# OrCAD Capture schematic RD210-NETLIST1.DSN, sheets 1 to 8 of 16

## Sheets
1 16: size Custom
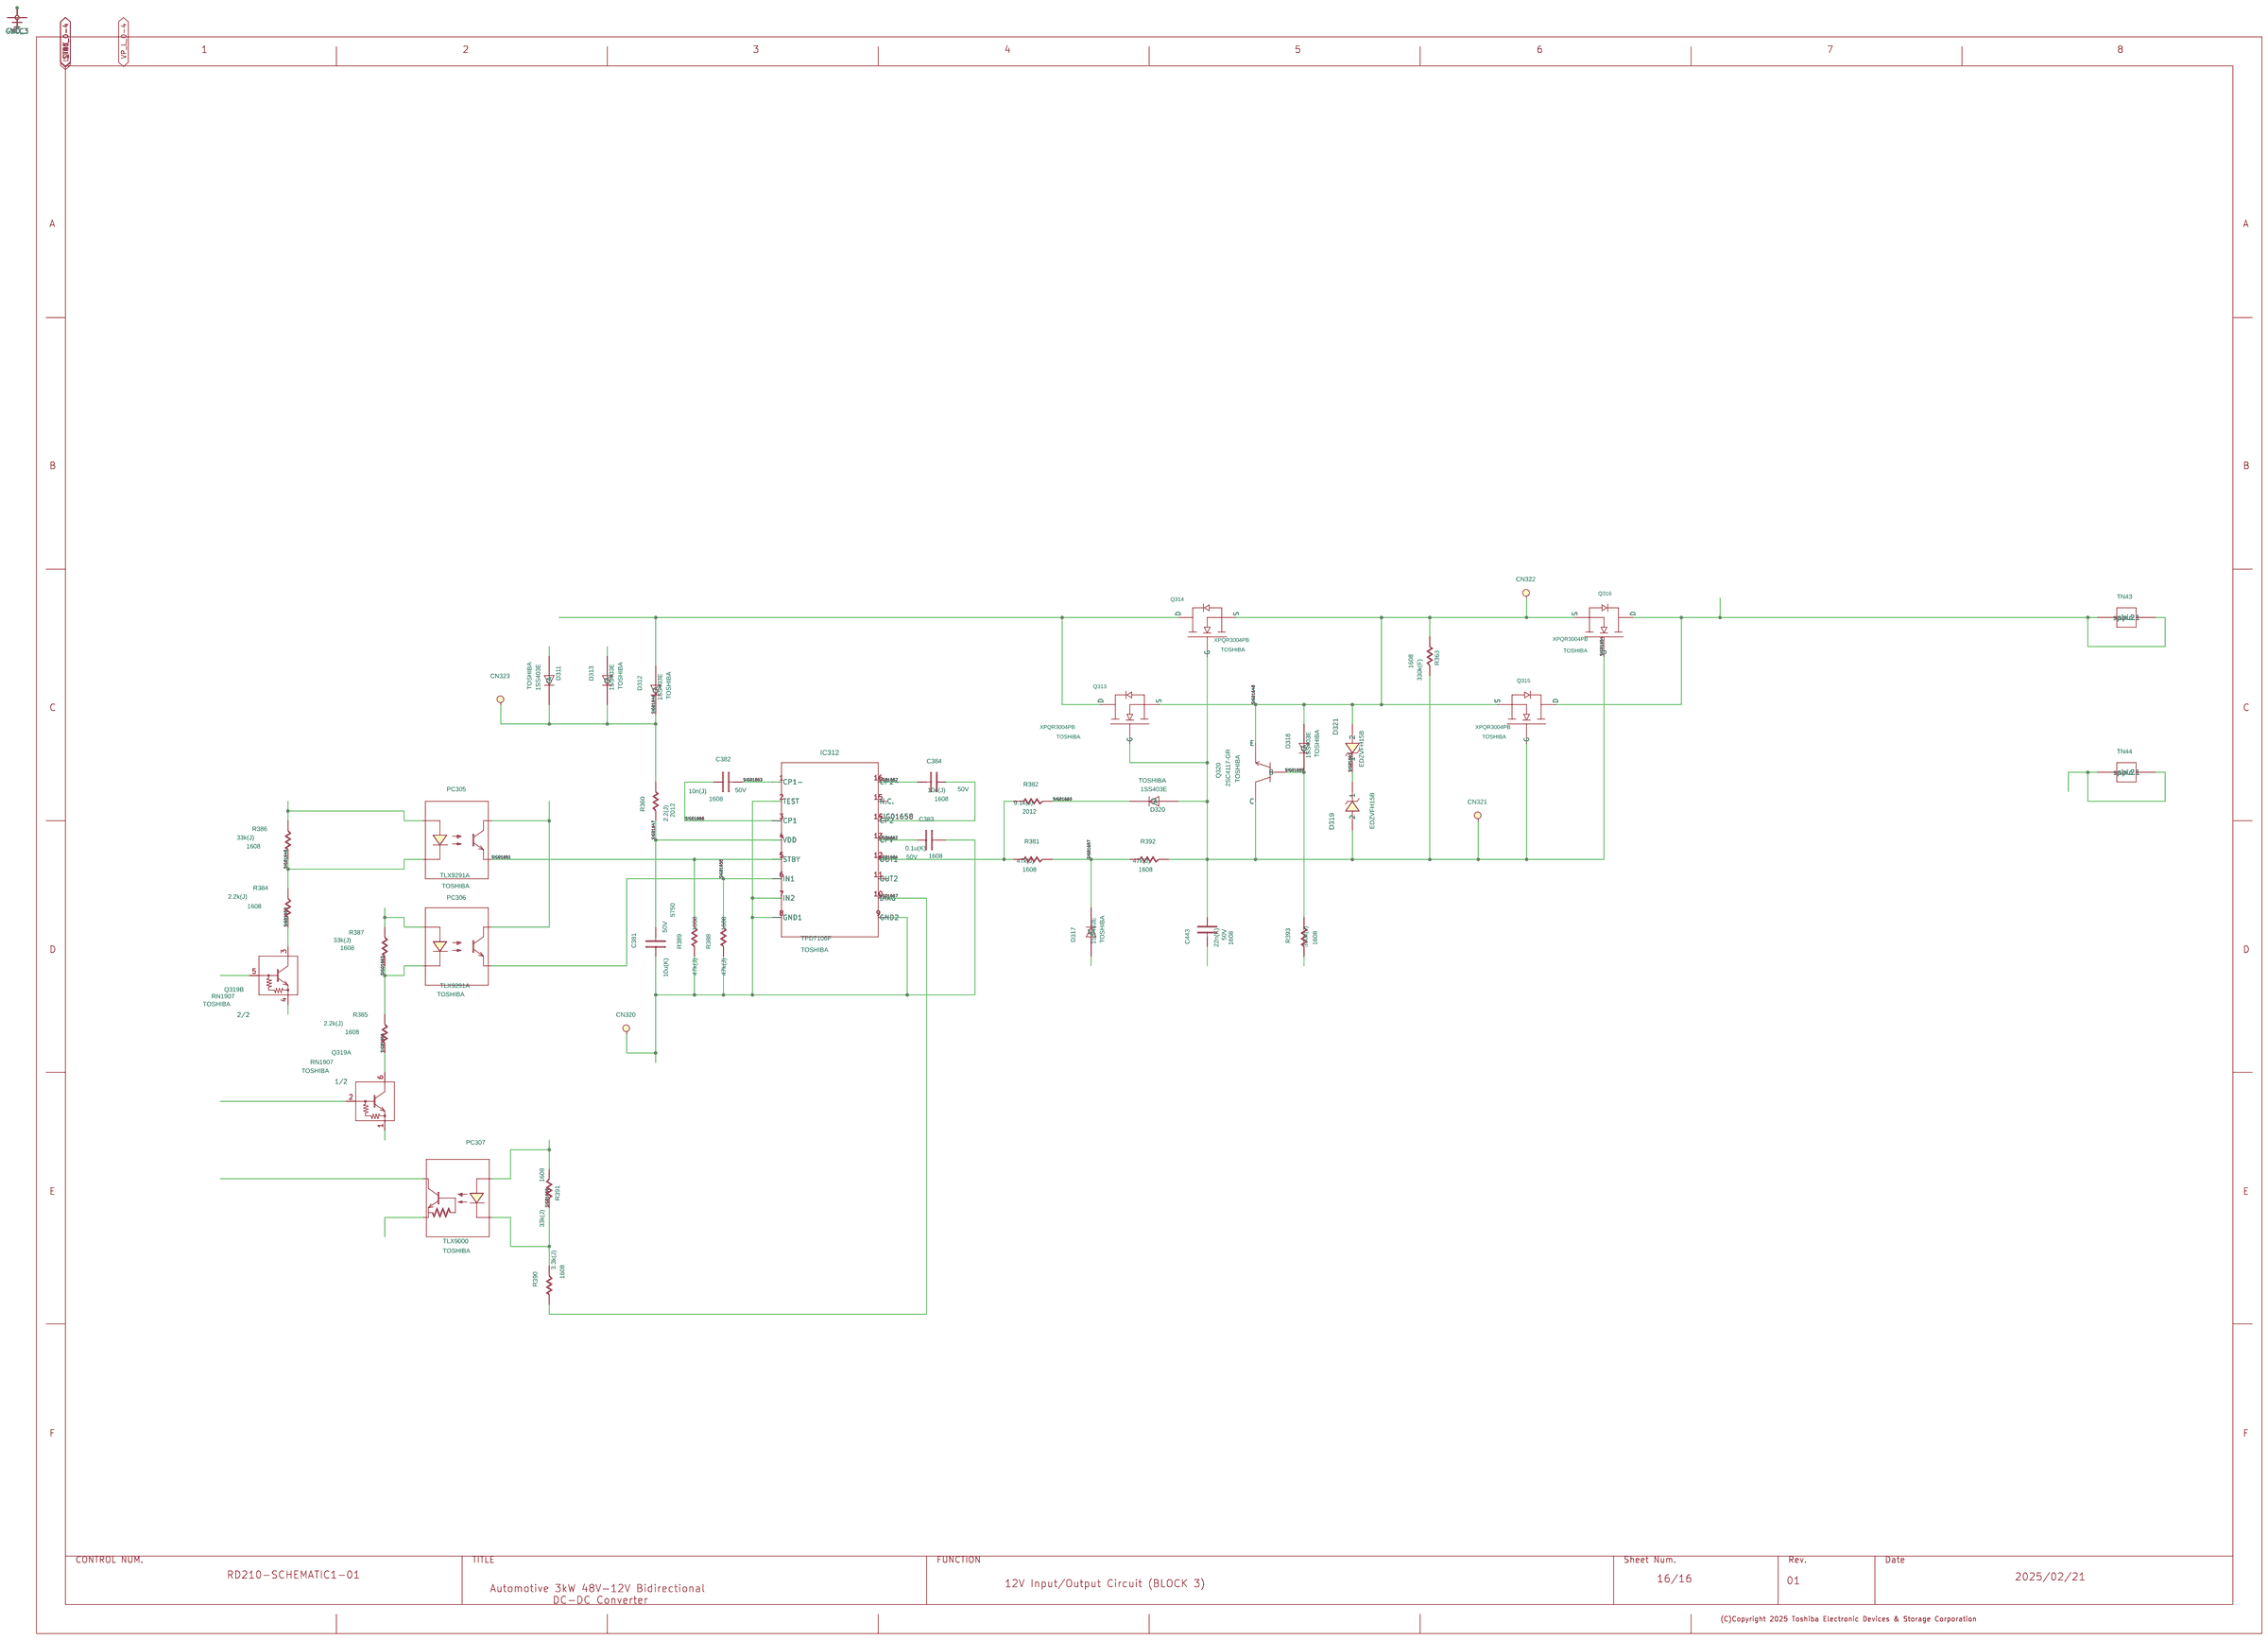
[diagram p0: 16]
2 15: size Custom
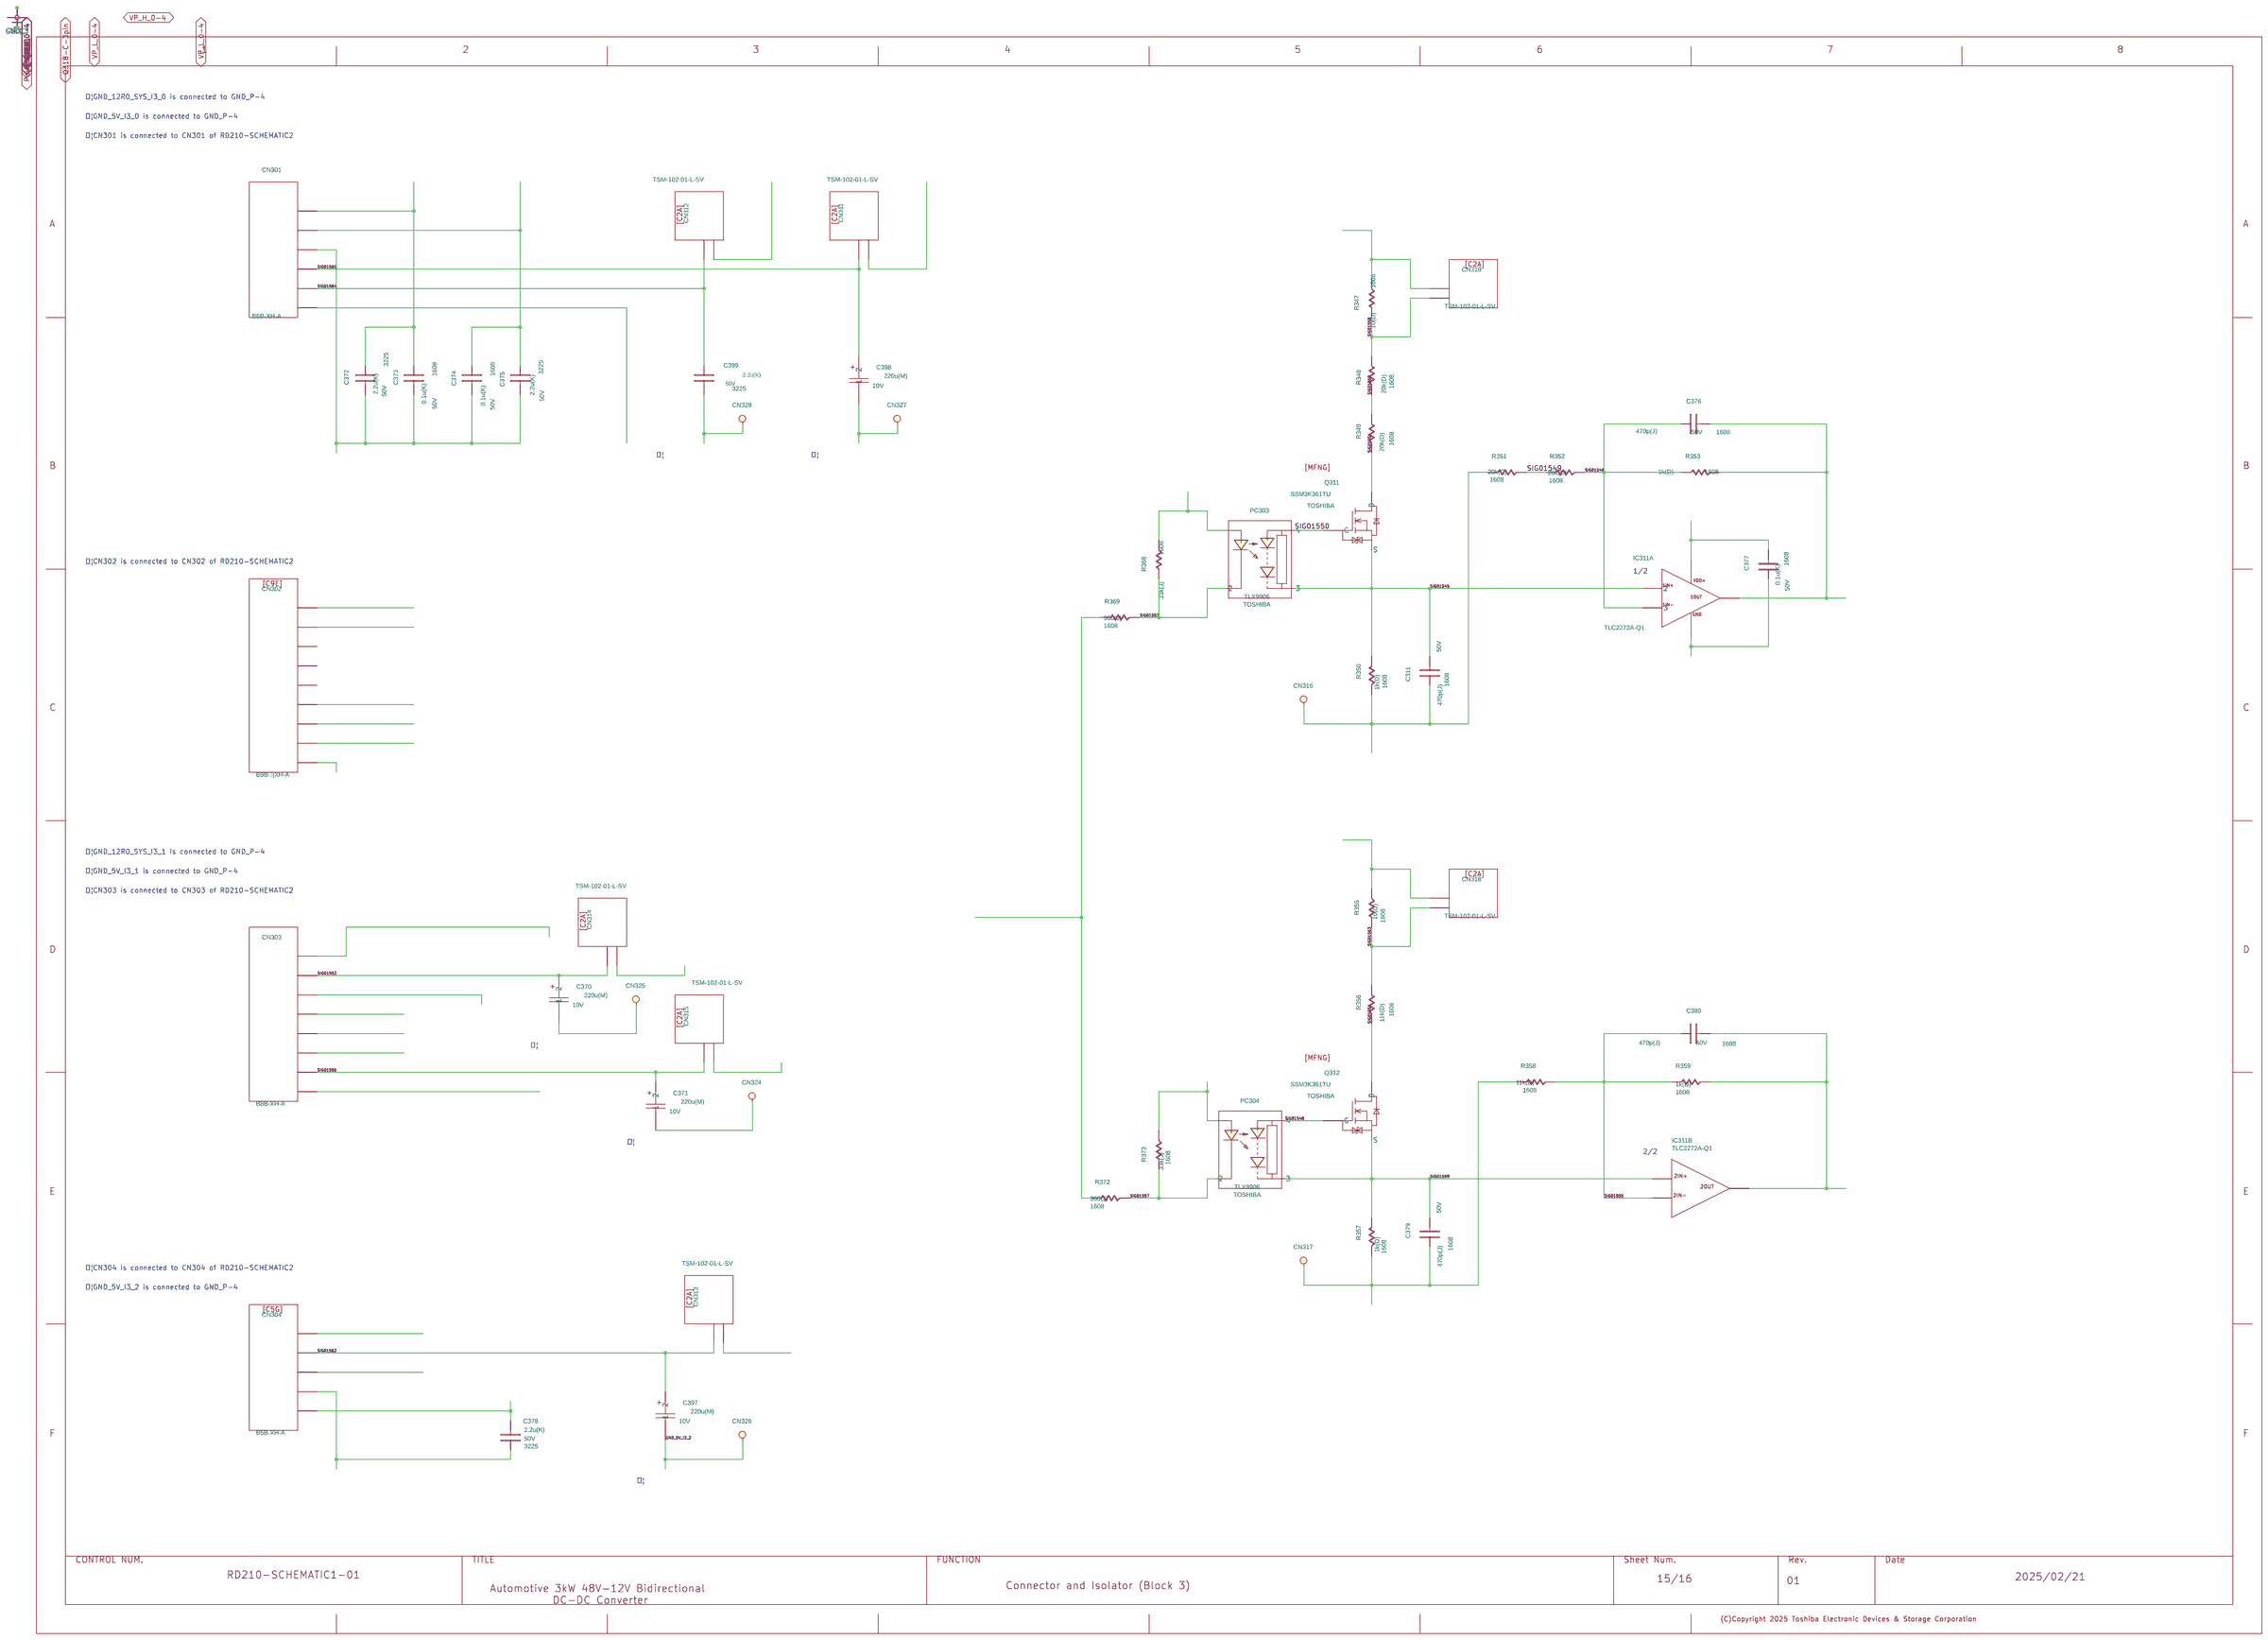
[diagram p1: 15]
3 14: size Custom
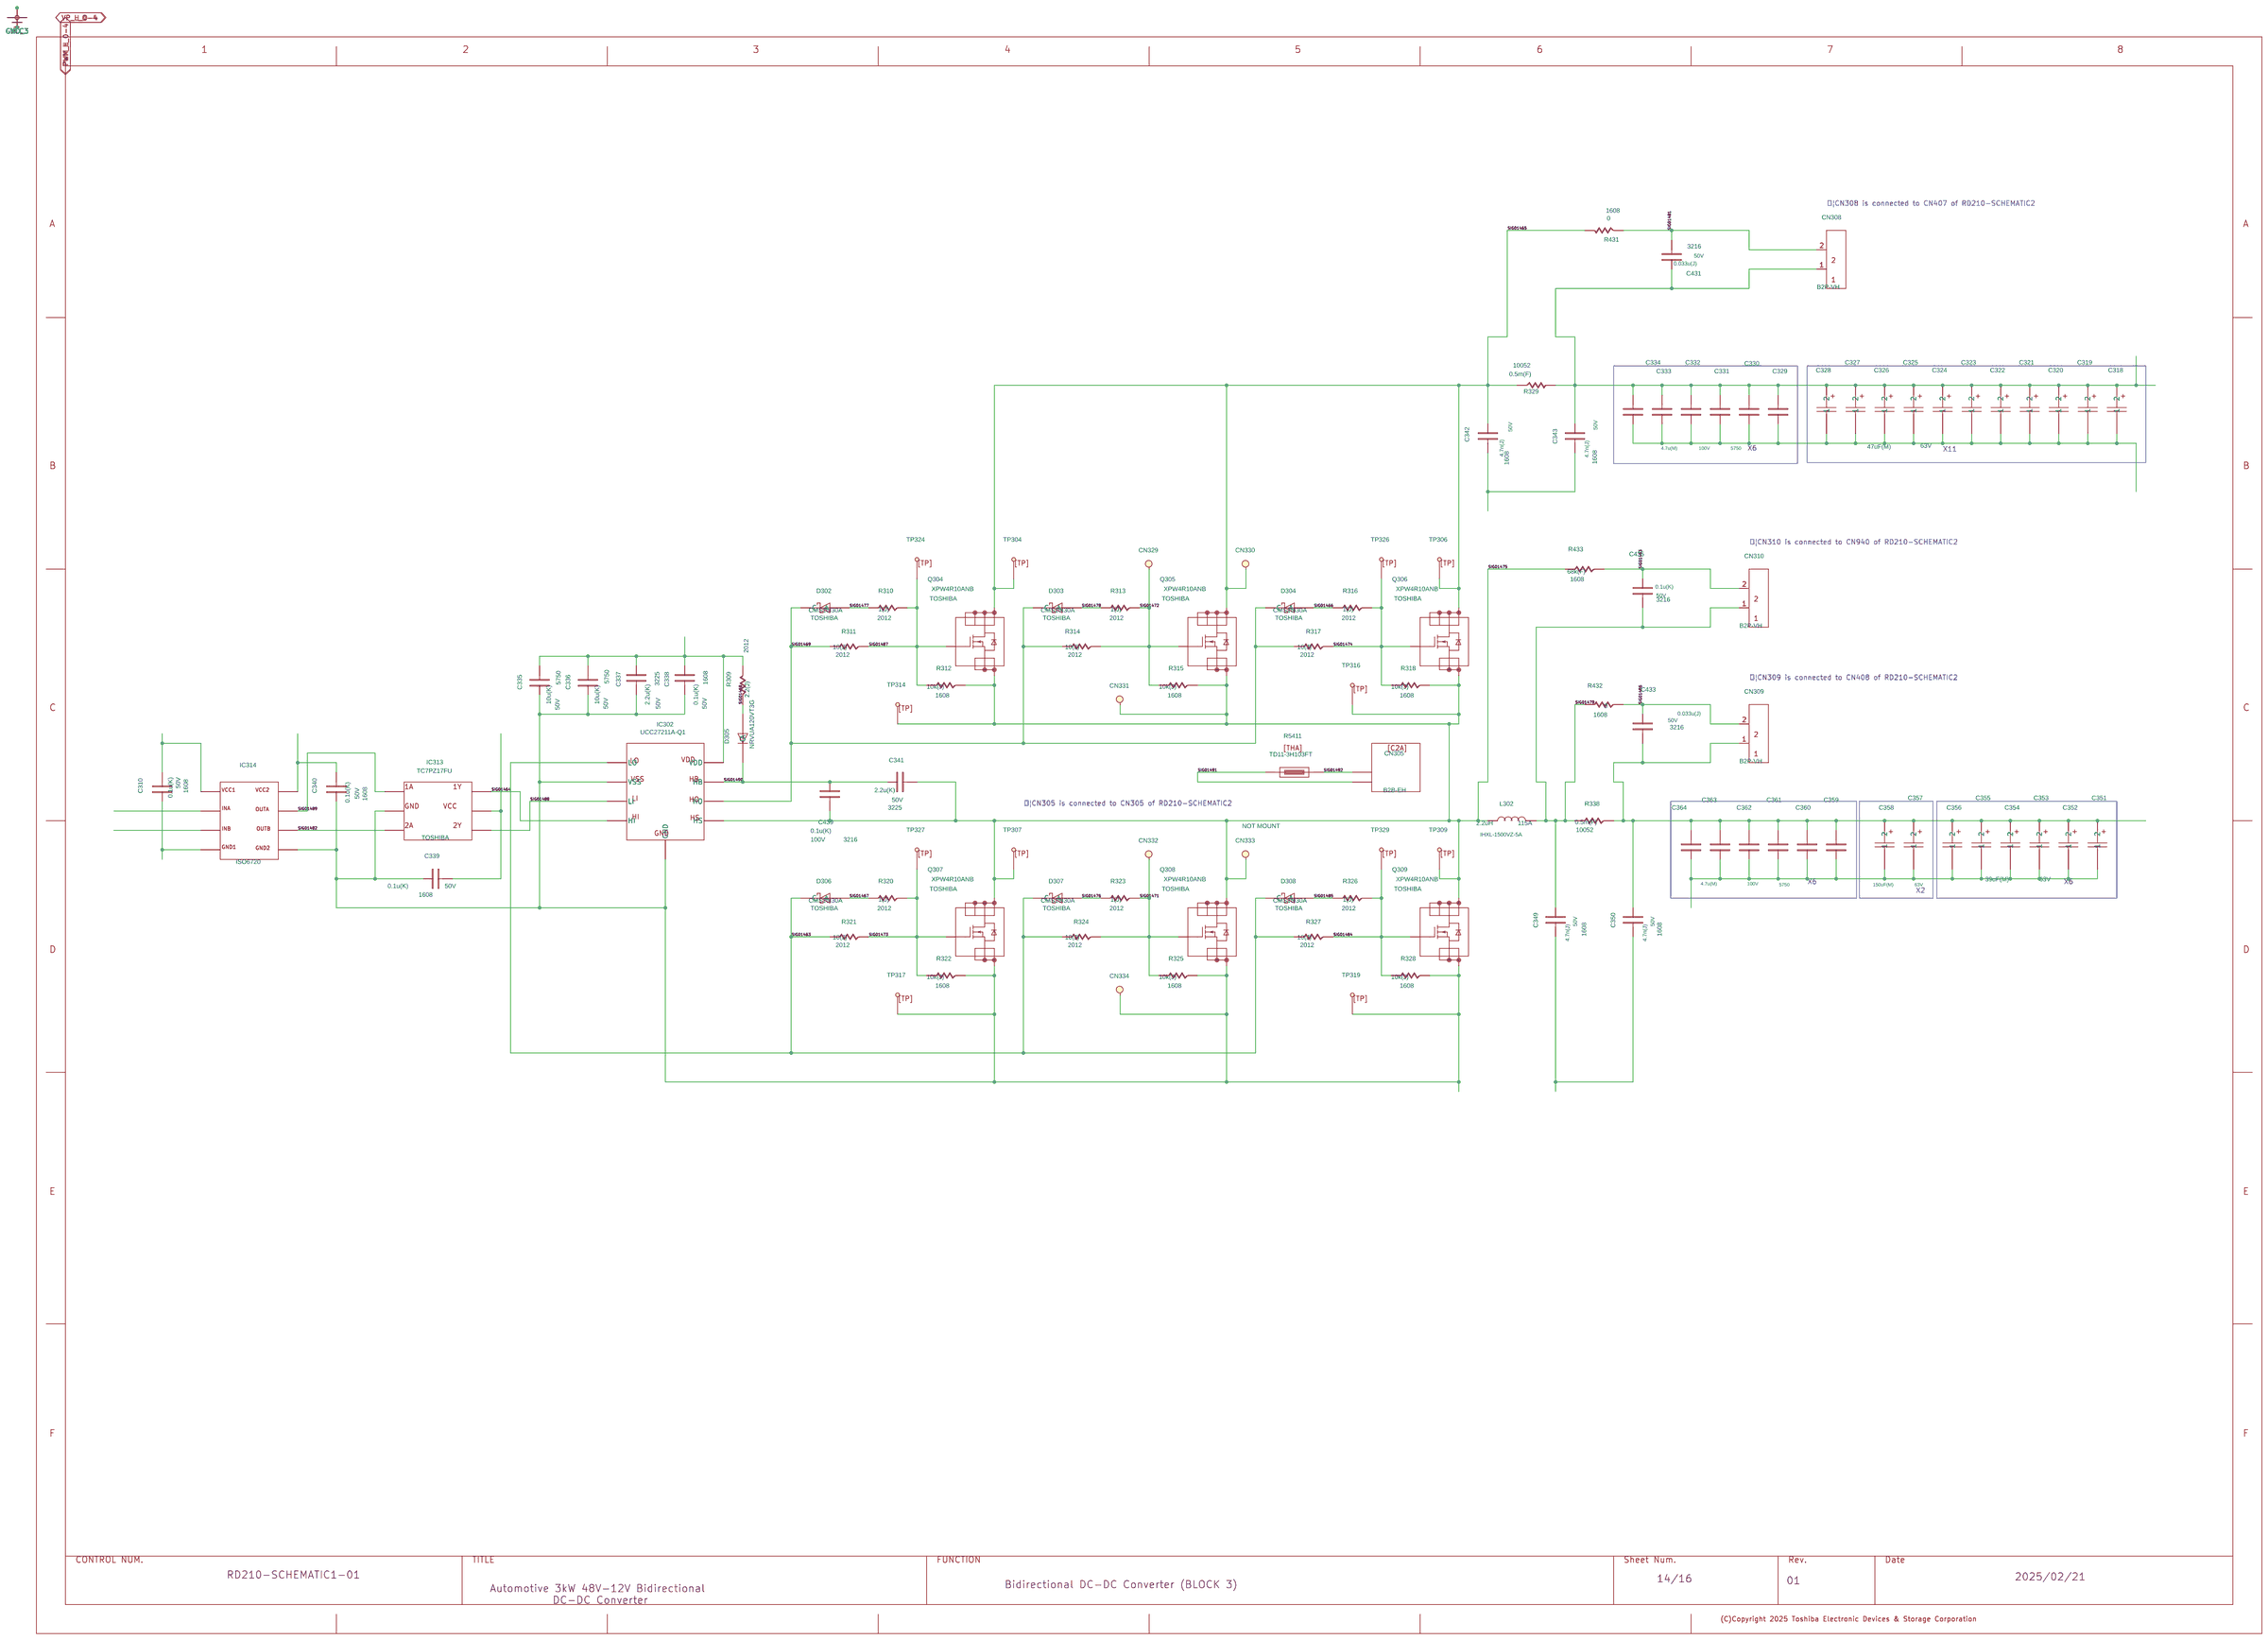
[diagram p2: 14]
4 13: size Custom
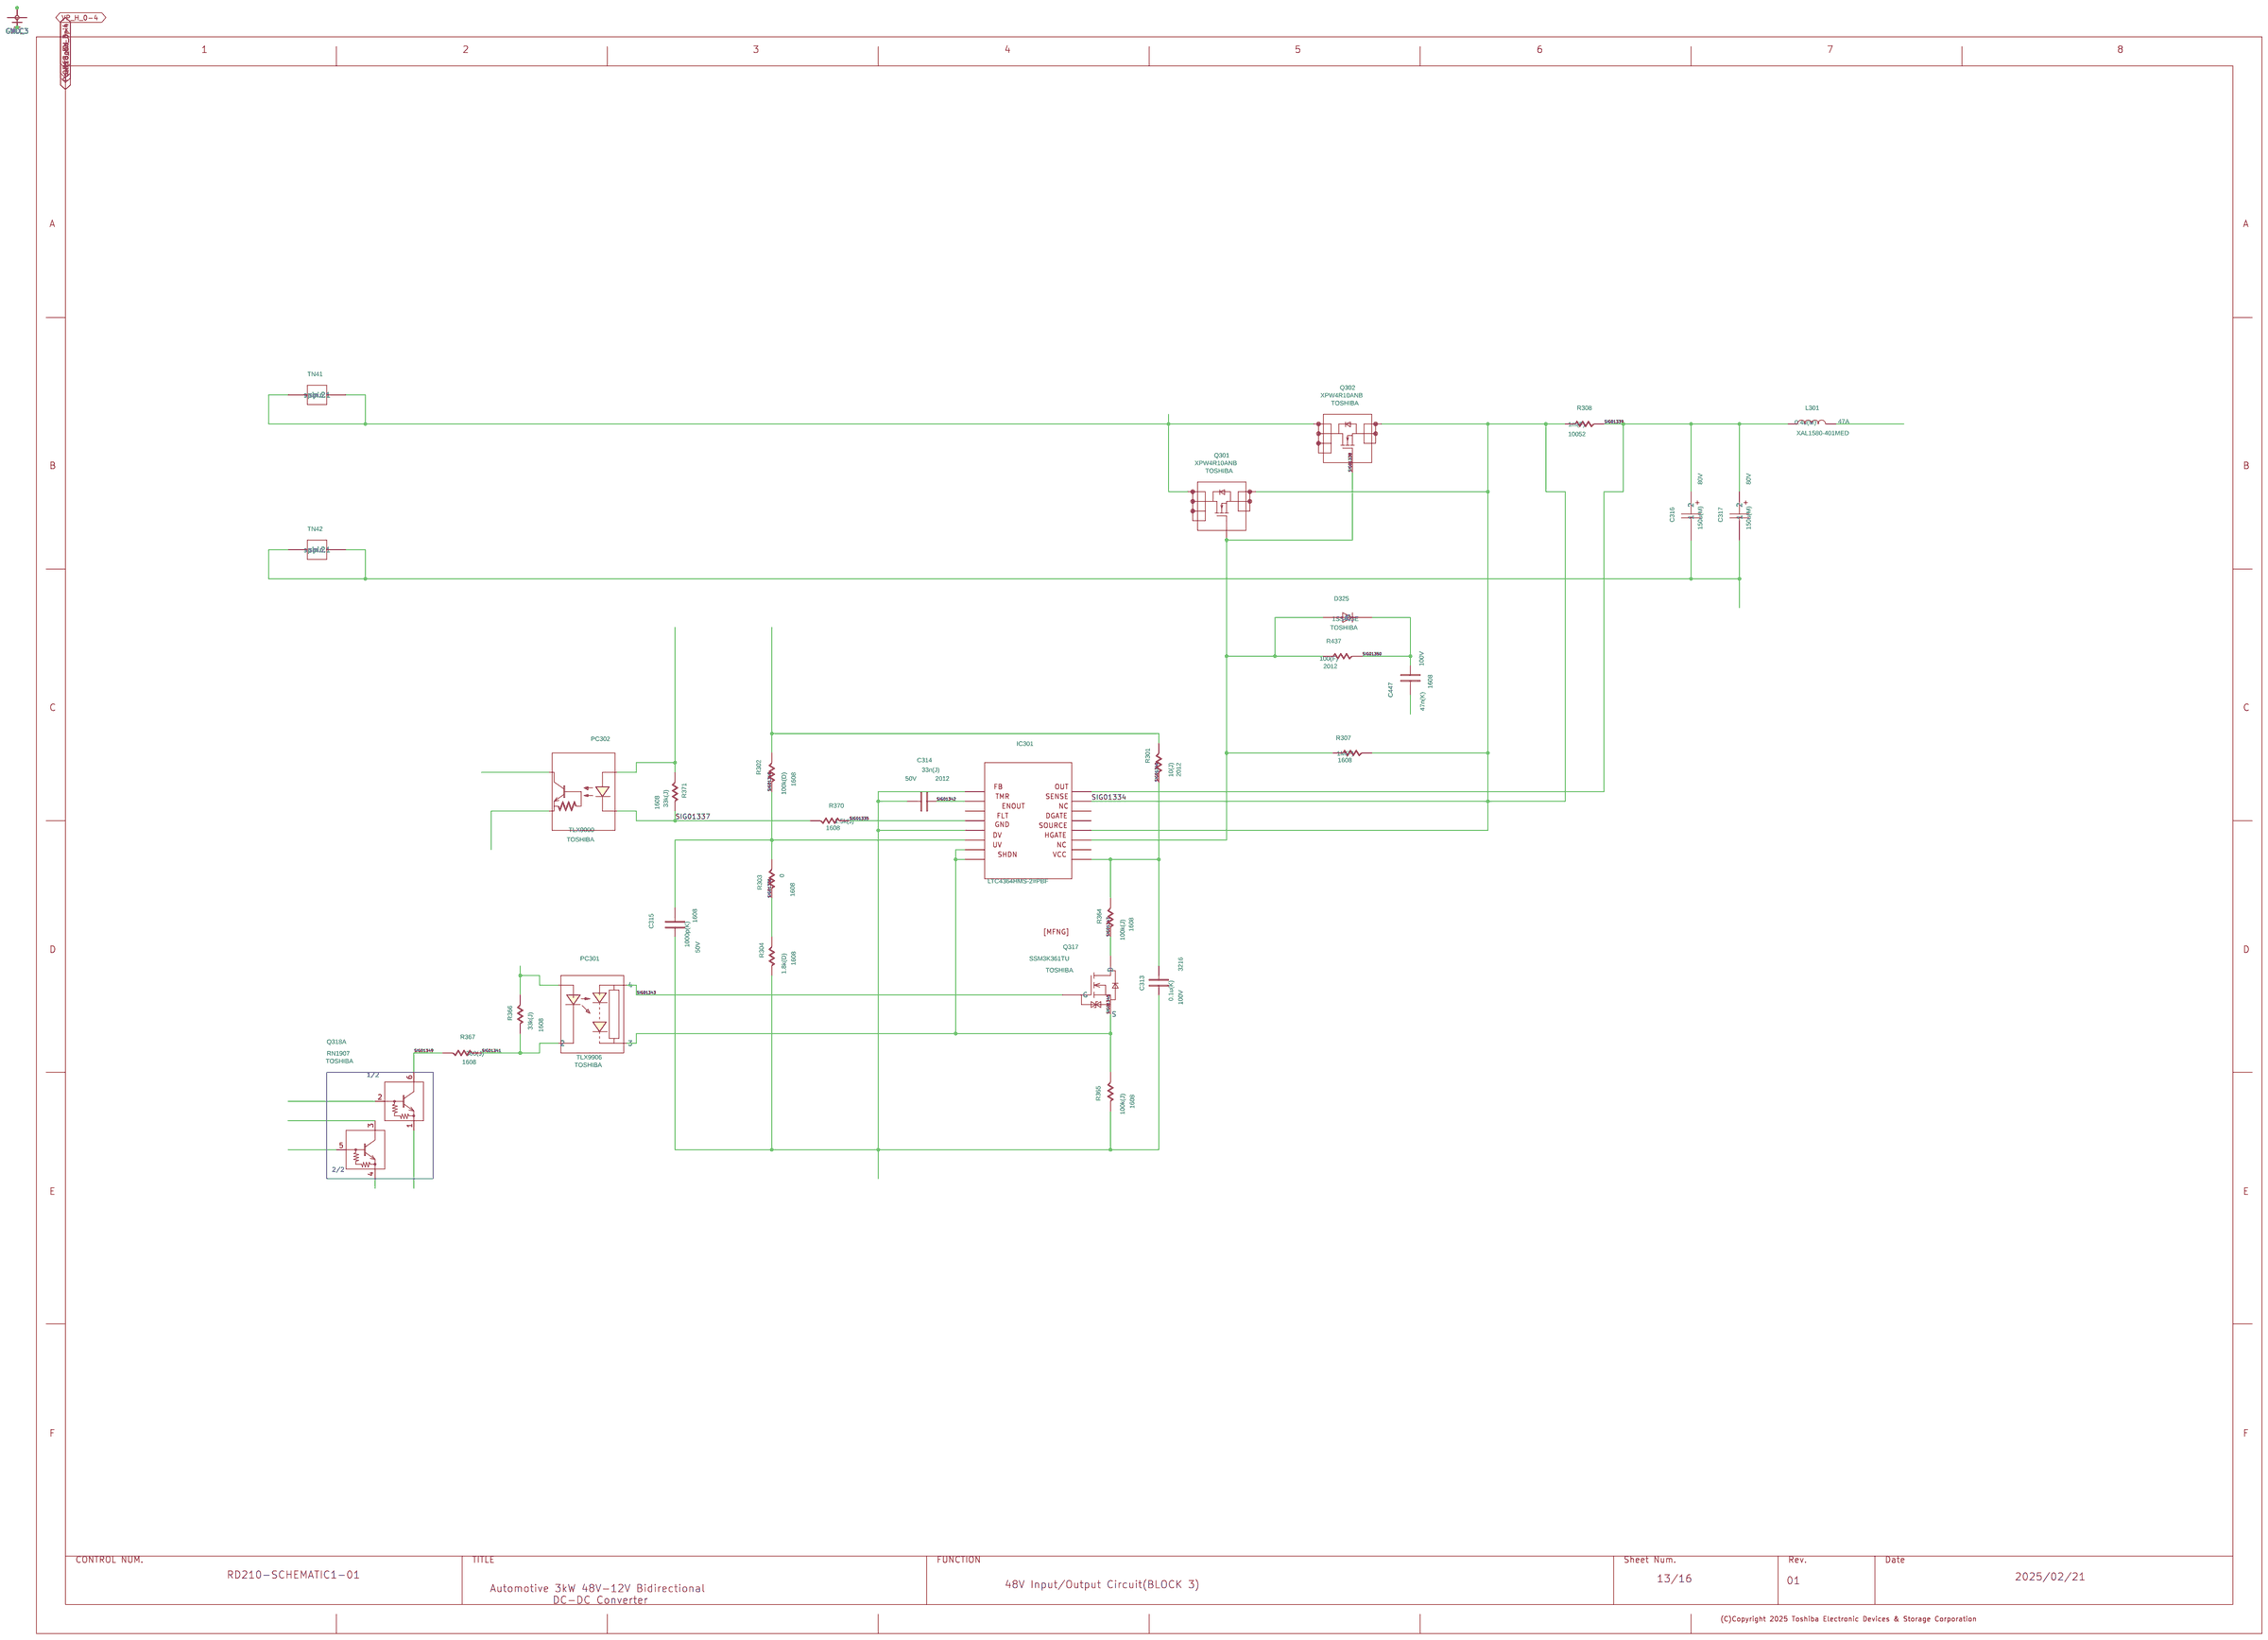
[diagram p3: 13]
5 12: size Custom
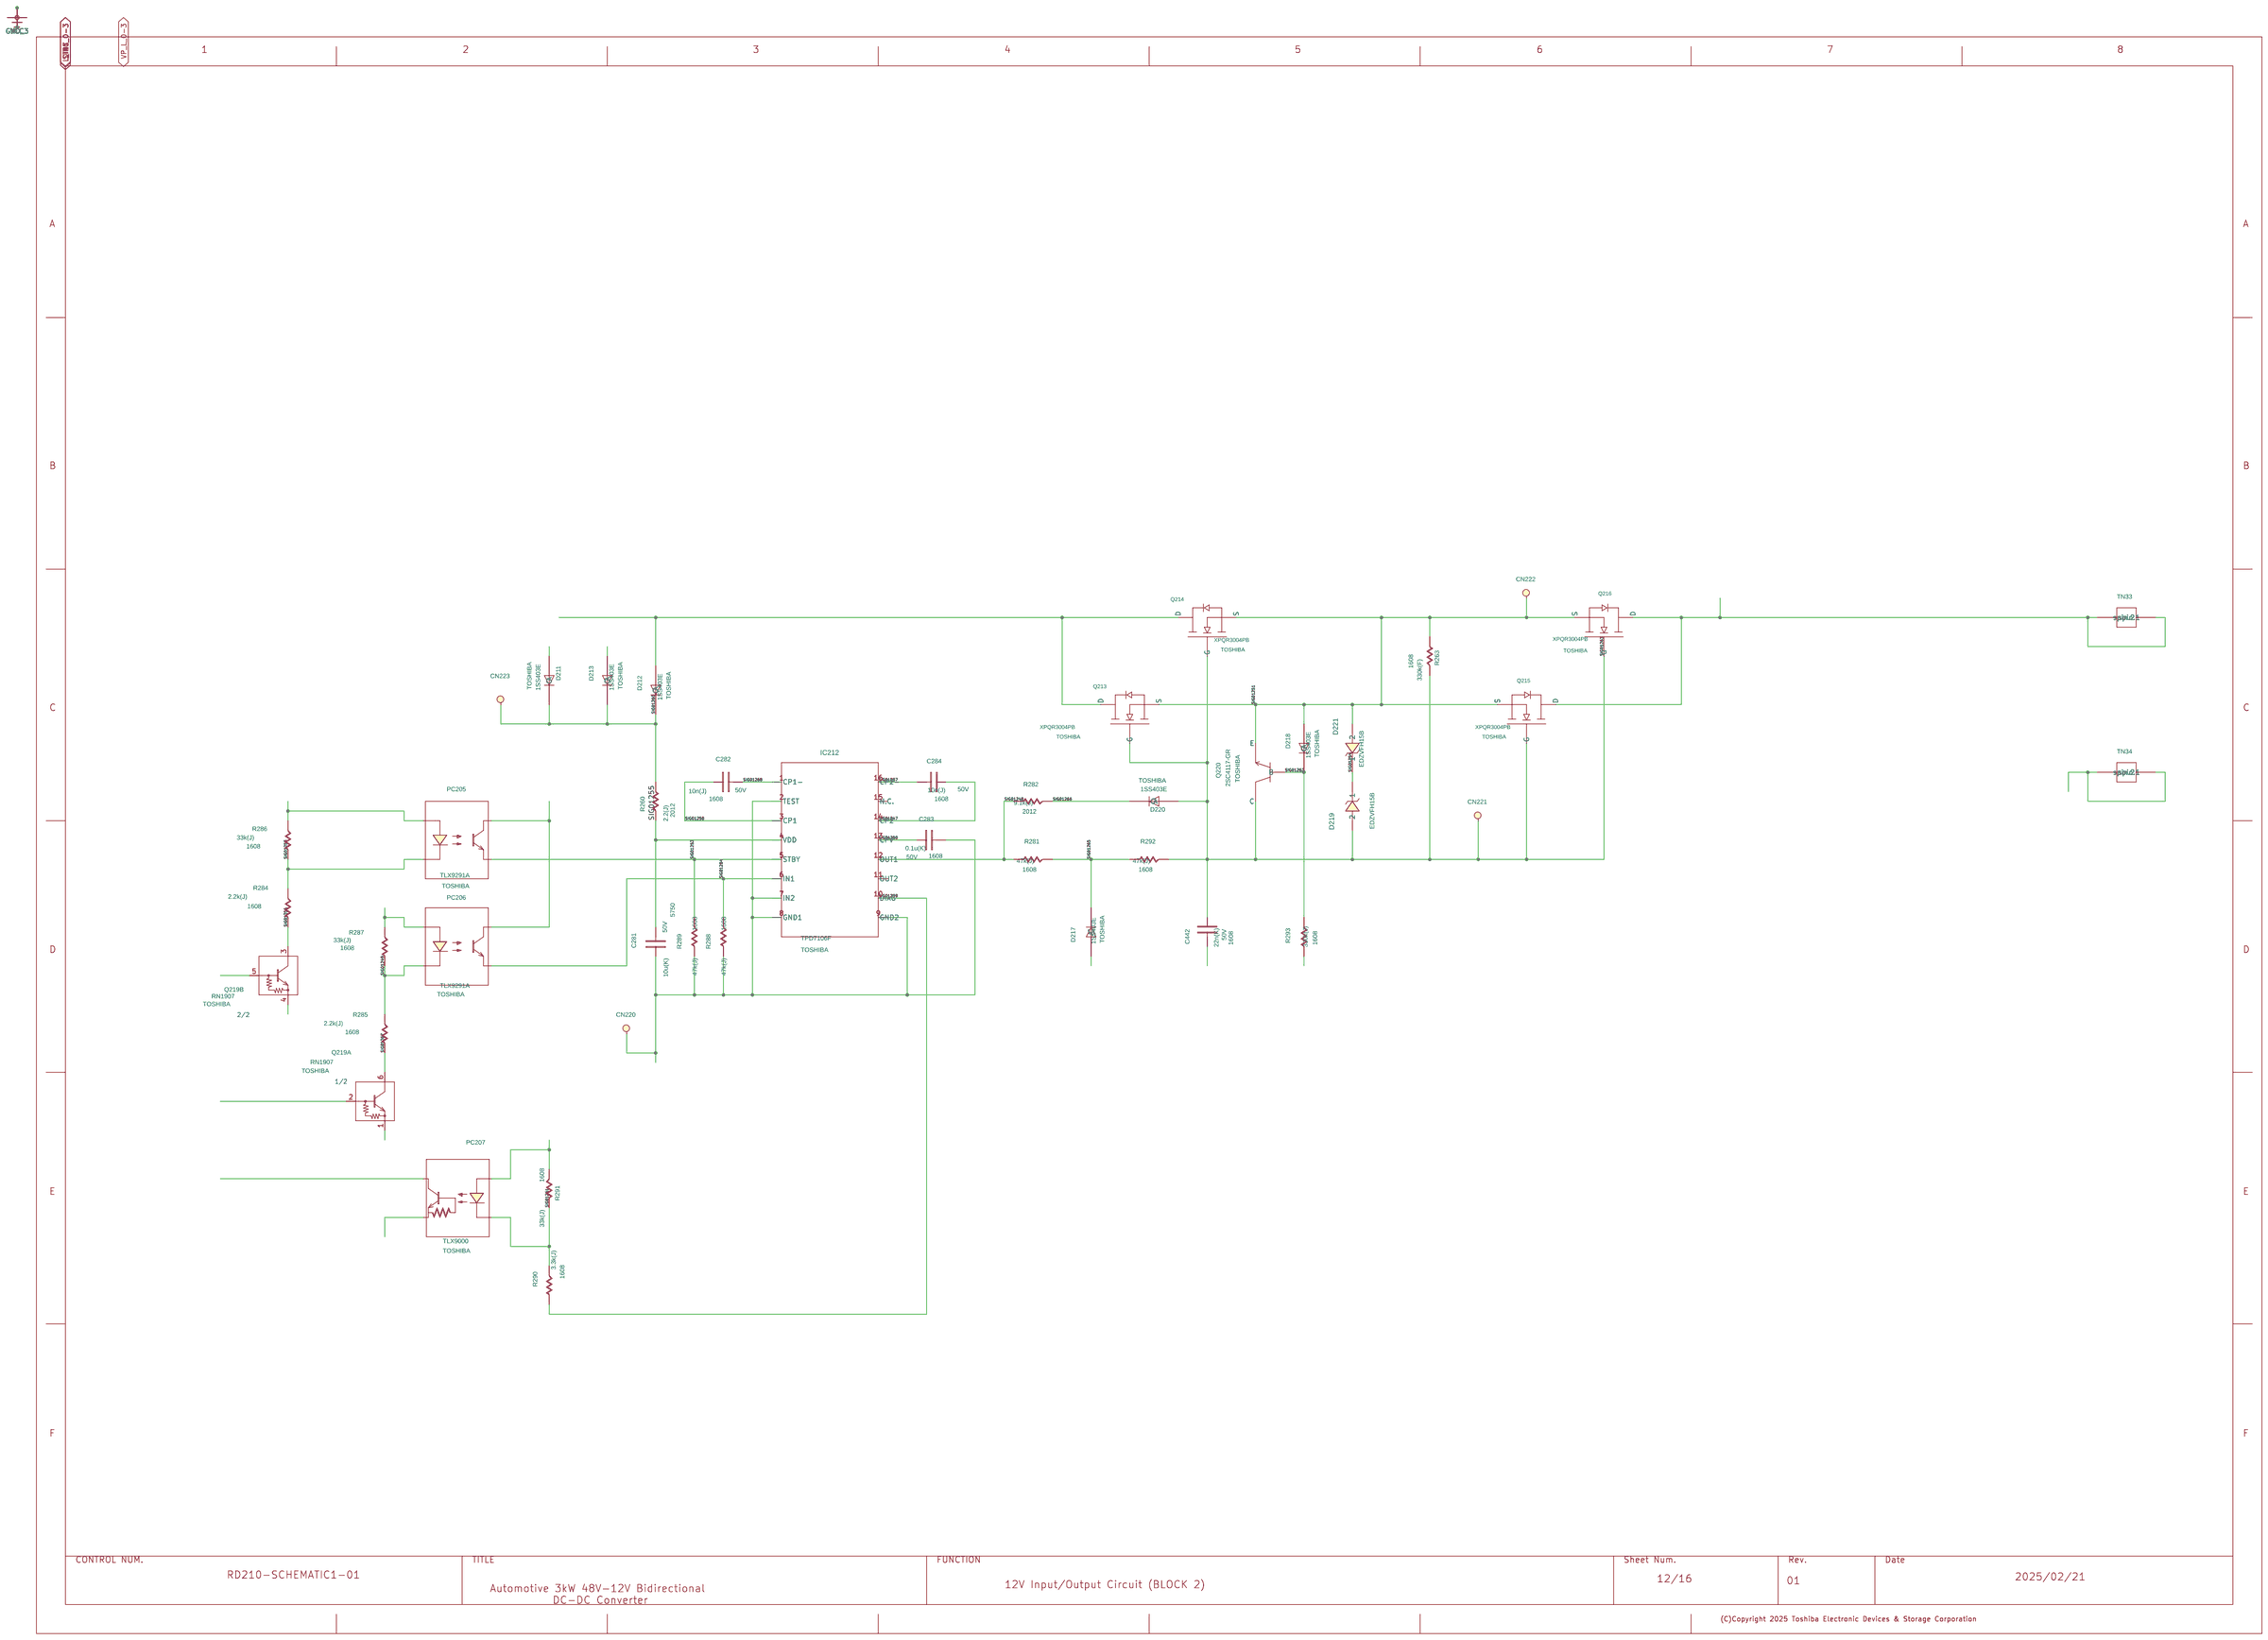
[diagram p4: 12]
6 11: size Custom
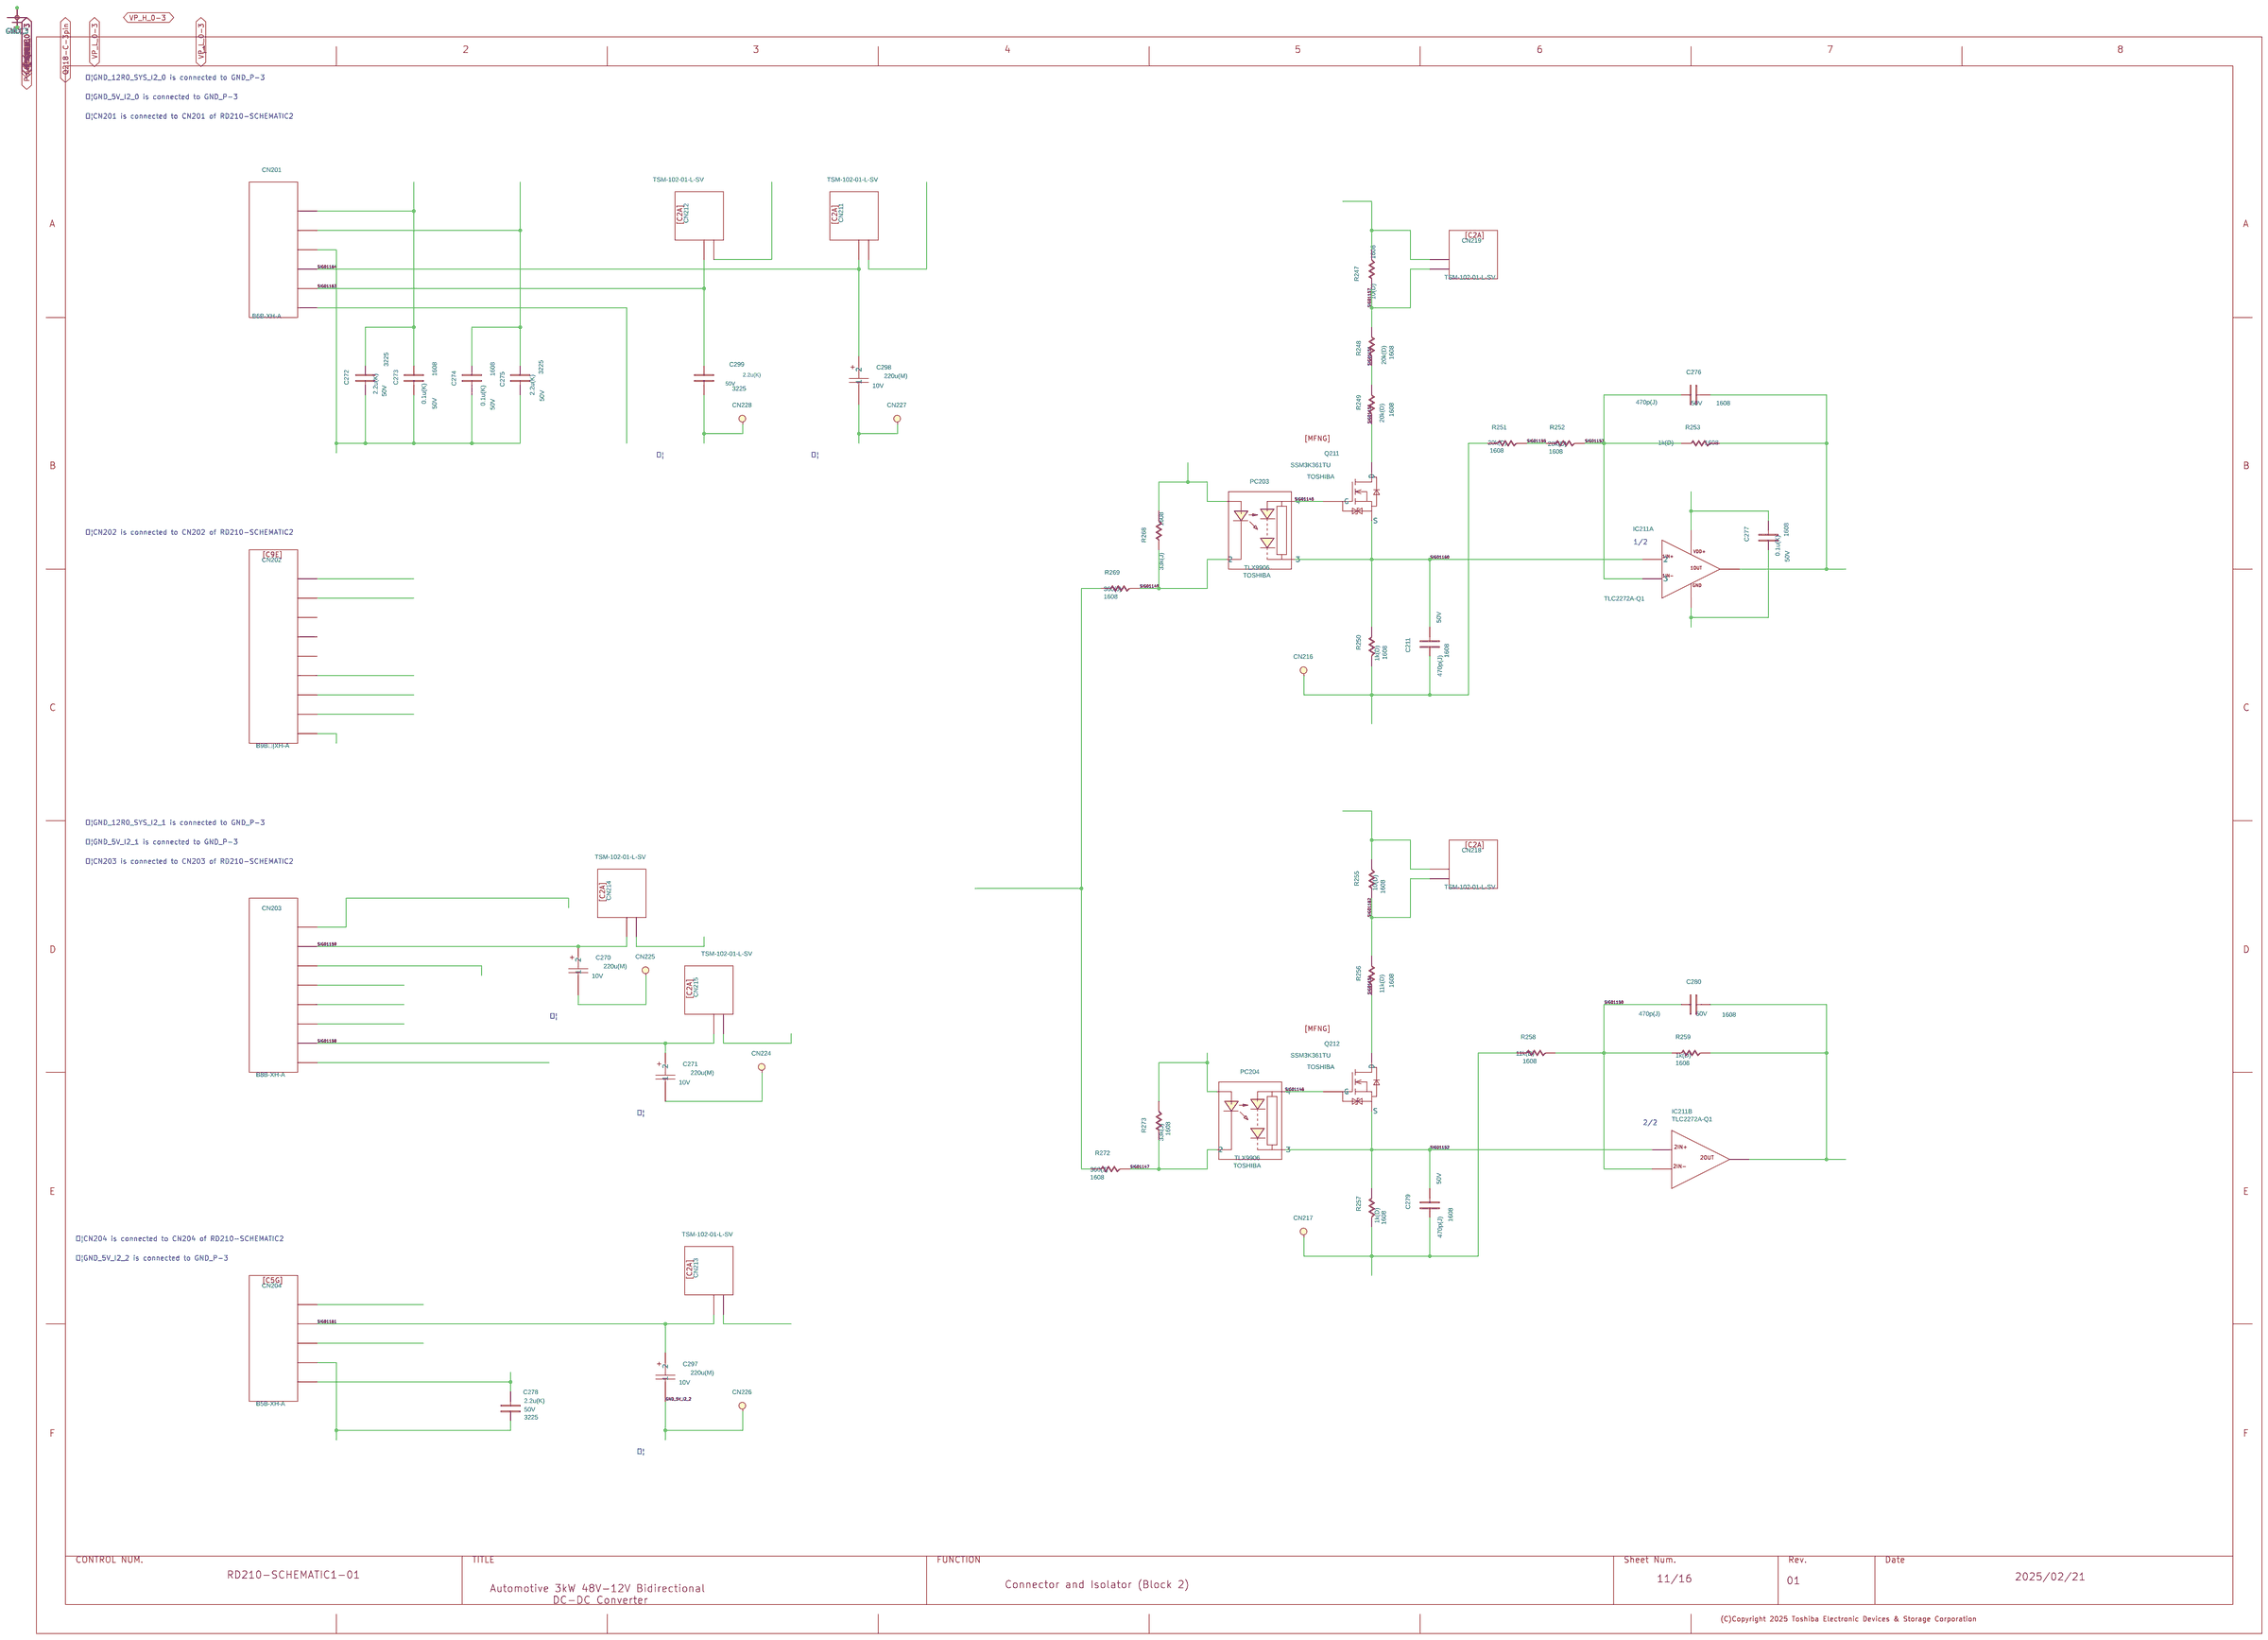
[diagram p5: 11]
7 10: size Custom
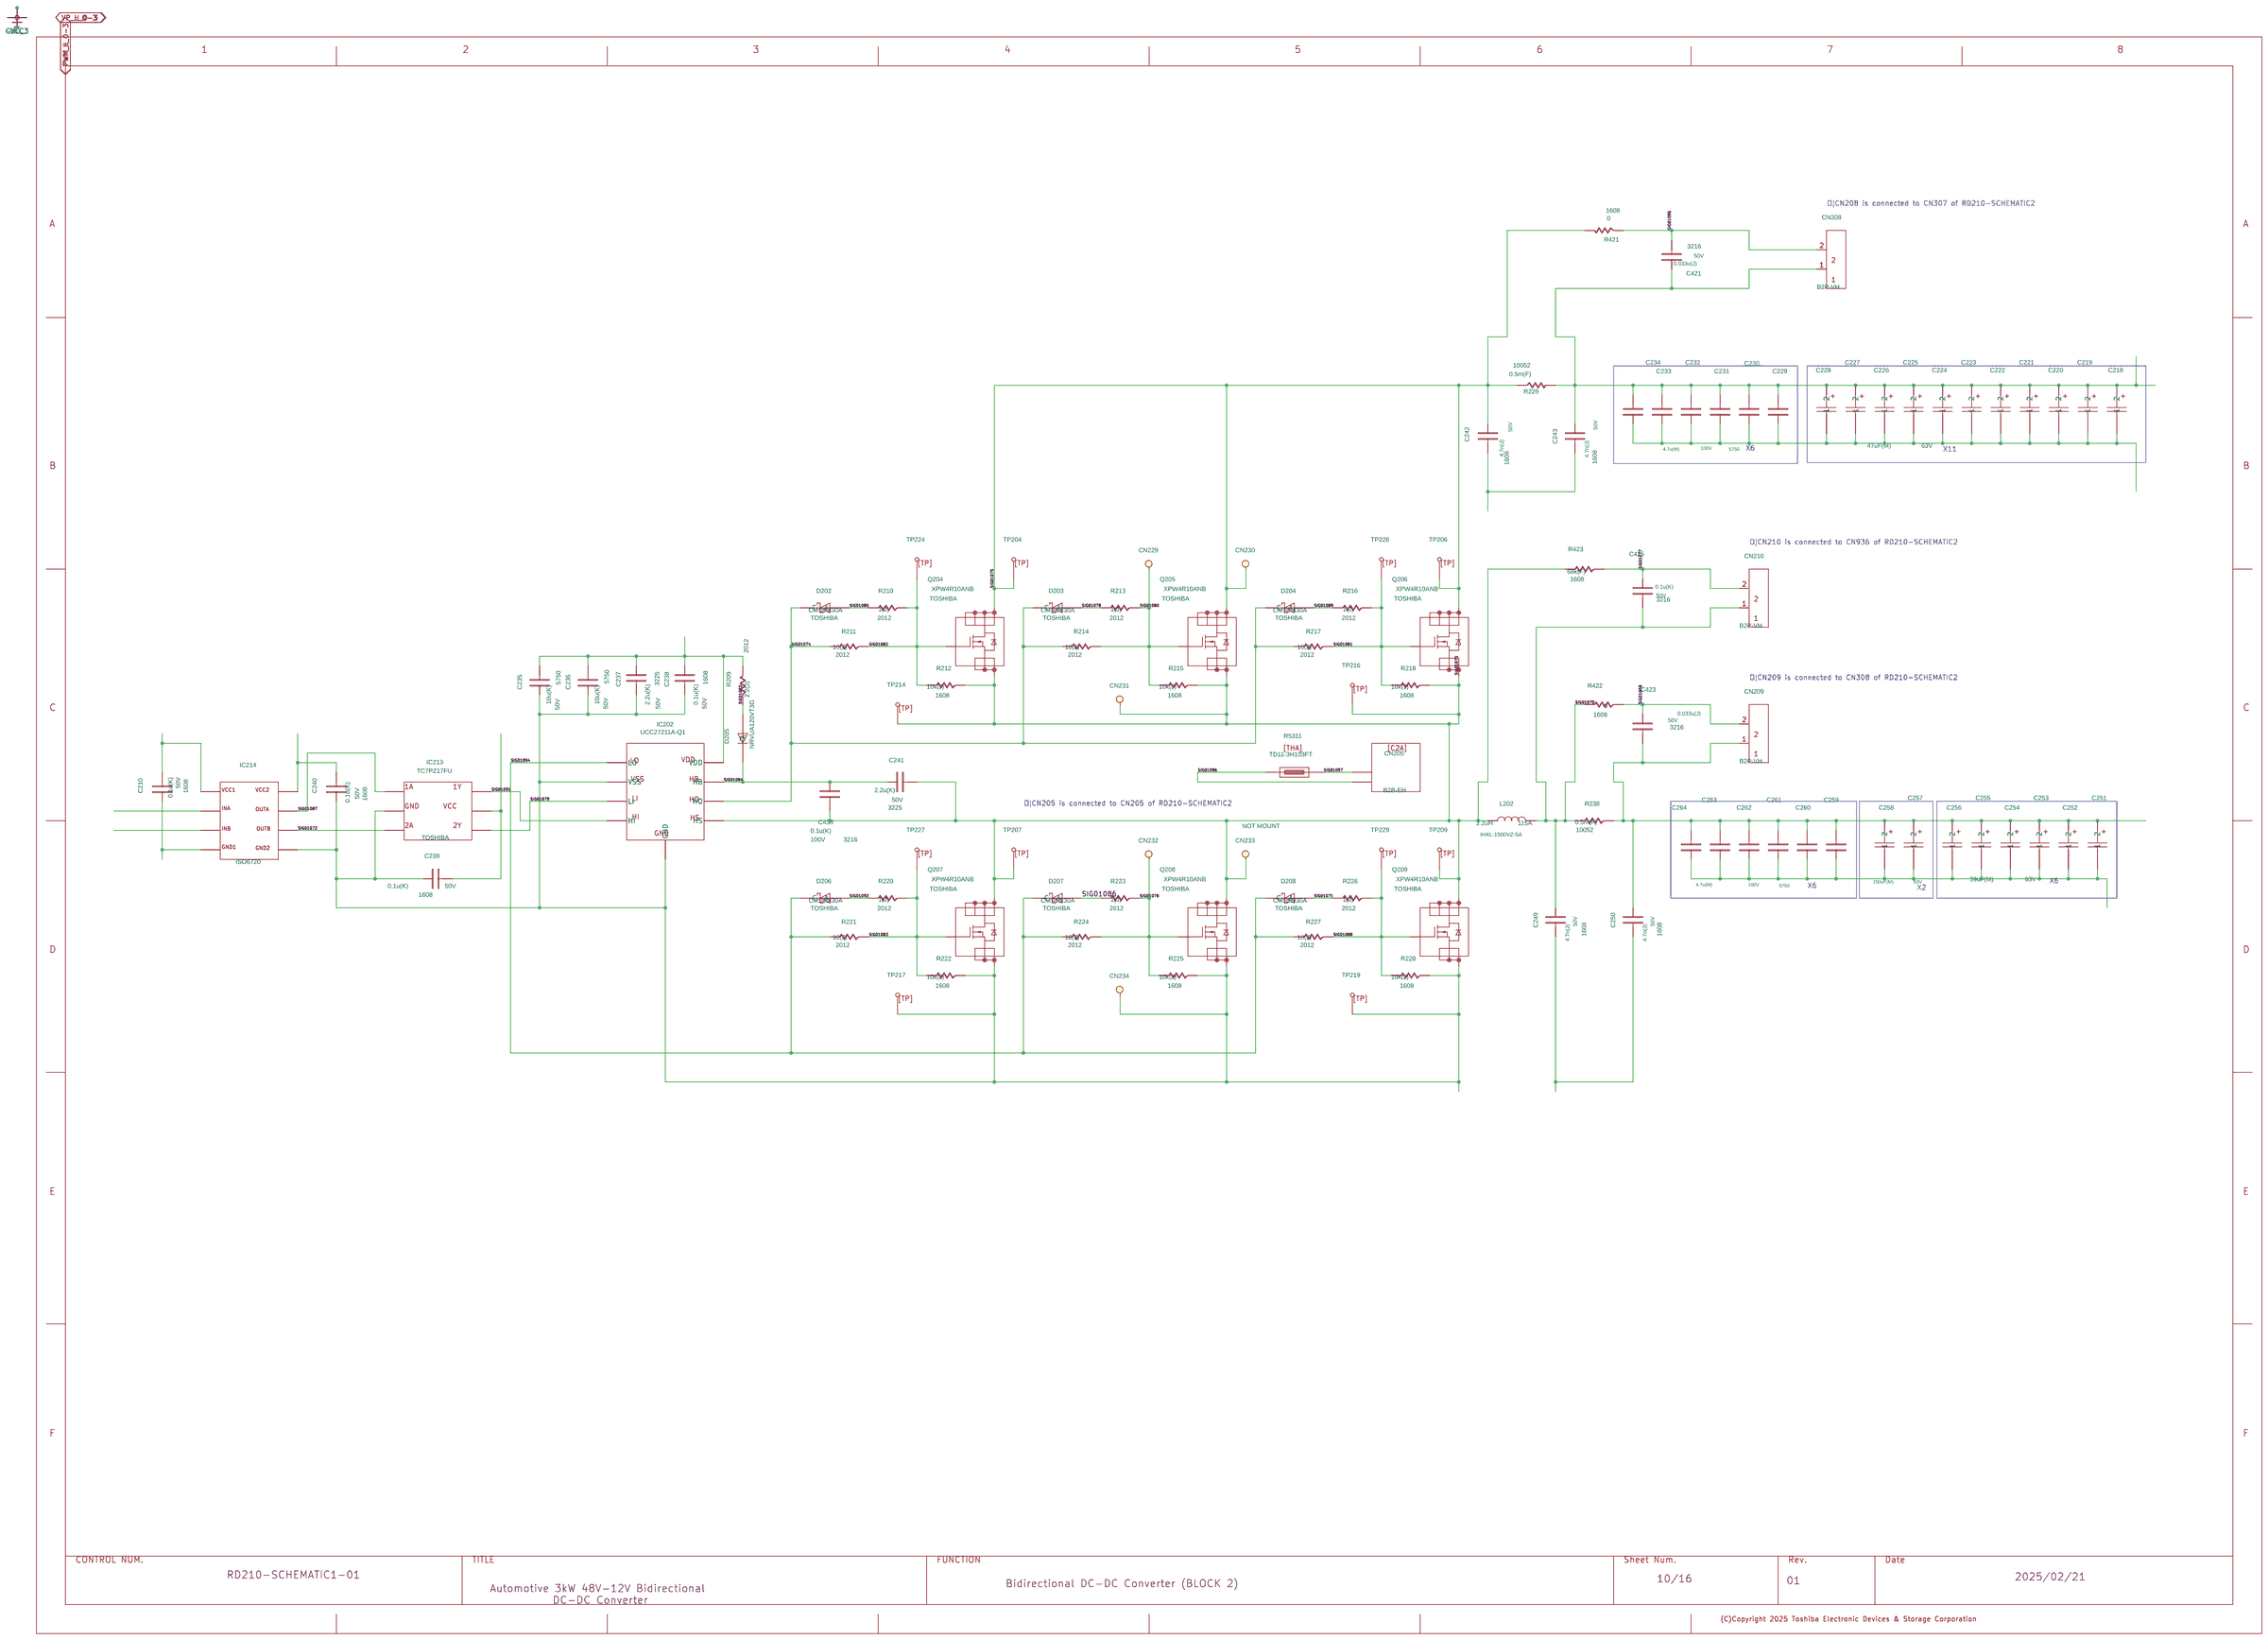
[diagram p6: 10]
8 9: size Custom
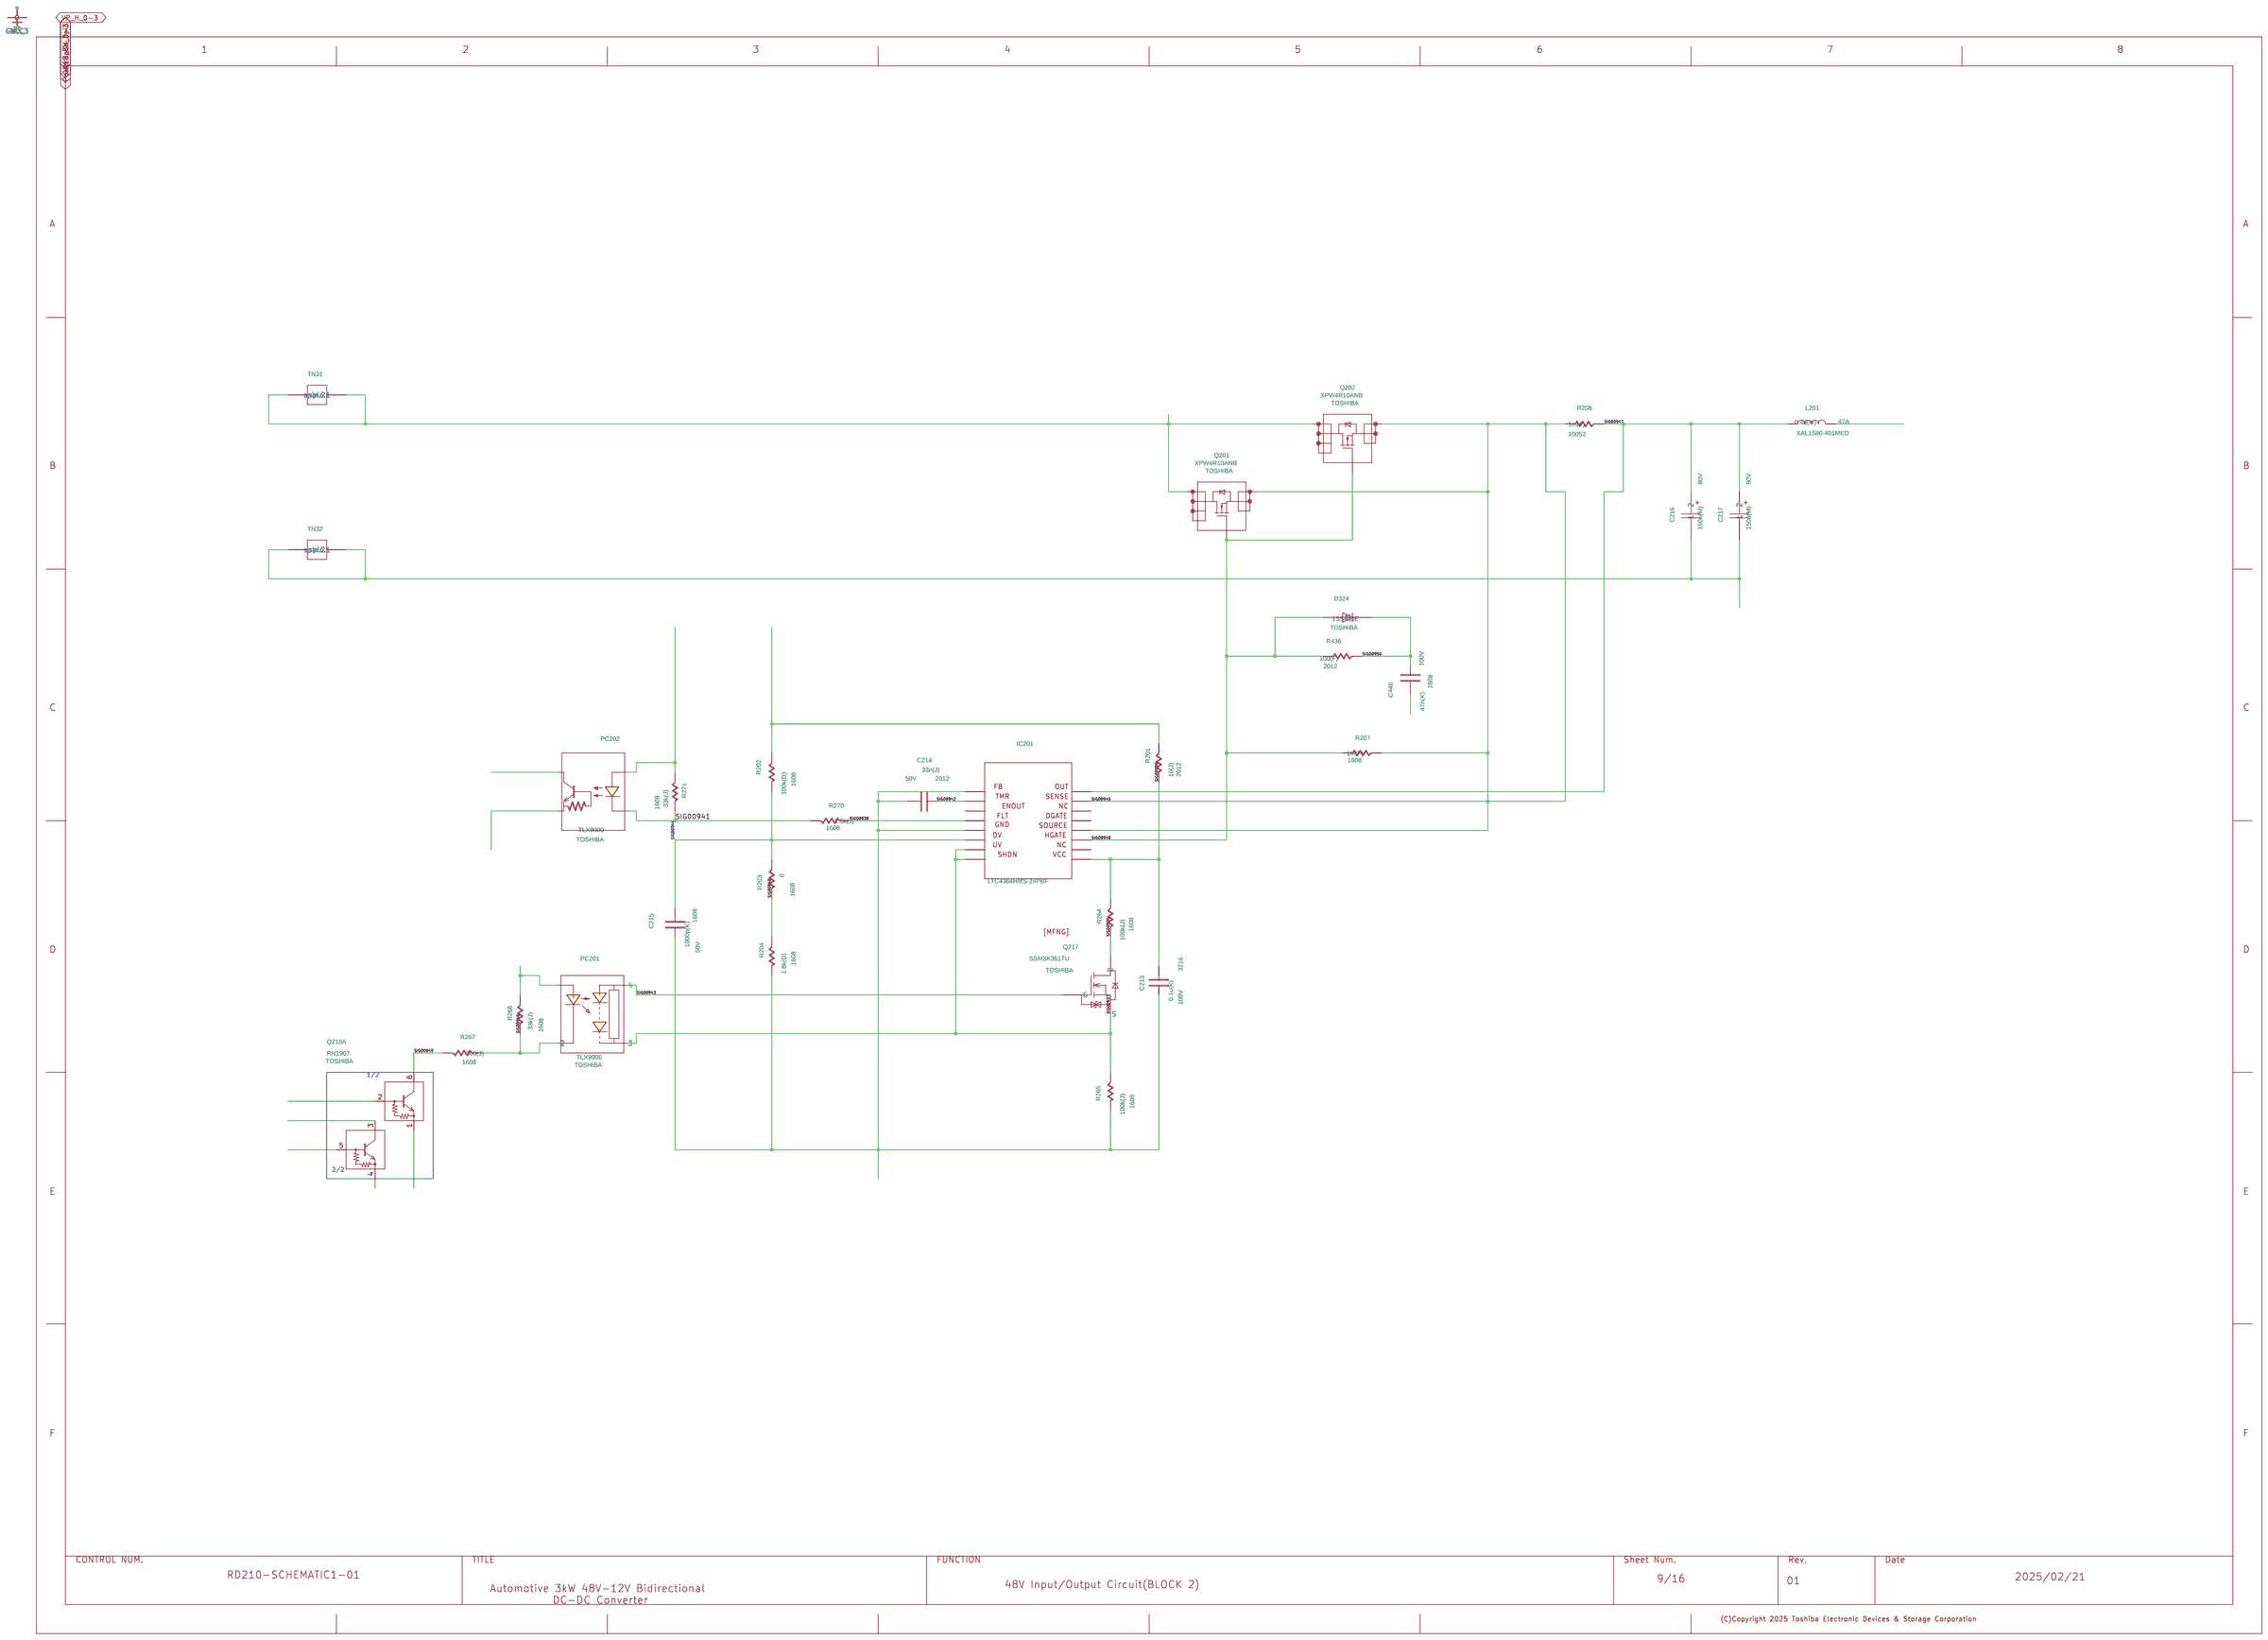
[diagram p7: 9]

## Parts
sheet 9
C213  C
C214  C
C215  C
C216  CP
C217  CP
C446  C
D324  D
IC201  IS18
L201  L
PC201  TLX9906
PC202  TLX9000
Q201  MFNAJ_1
Q202  MFNAJ_1
Q217  MFNG
Q218  RN1907_Q1_1  (sections A,B)
R201  R
R202  R
R203  R
R204  R
R207  R
R208  R
R264  R
R265  R
R266  R
R267  R
R270  R
R271  R
R436  R
TN31  BOX_2
TN32  BOX_2
U?#7  WAKU_DEF_A3
sheet 10
C210  C
C218  CP
C219  CP
C220  CP
C221  CP
C222  CP
C223  CP
C224  CP
C225  CP
C226  CP
C227  CP
C228  CP
C229  C
C230  C
C231  C
C232  C
C233  C
C234  C
C235  C
C236  C
C237  C
C238  C
C239  C
C240  C
C241  C
C242  C
C243  C
C249  C
C250  C
C251  CP
C252  CP
C253  CP
C254  CP
C255  CP
C256  CP
C257  CP
C258  CP
C259  C
C260  C
C261  C
C262  C
C263  C
C264  C
C421  C
C423  C
C425  C
C438  C
CN205  C2A
CN208  B2P-VH
CN209  B2P-VH
CN210  B2P-VH
CN229  HM-TP08
CN230  HM-TP08
CN231  HM-TP08
CN232  HM-TP08
CN233  HM-TP08
CN234  HM-TP08
D202  SBD
D203  SBD
D204  SBD
D205  D
D206  SBD
D207  SBD
D208  SBD
IC202  UCC27211A_00
IC213  TC7PZ17FU
IC214  ISO6720_IC13
L202  L
Q204  MFNAJ_1
Q205  MFNAJ_1
Q206  MFNAJ_1
Q207  MFNAJ_1
Q208  MFNAJ_1
Q209  MFNAJ_1
R209  R
R210  R
R211  R
R212  R
R213  R
R214  R
R215  R
R216  R
R217  R
R218  R
R220  R
R221  R
R222  R
R223  R
R224  R
R225  R
R226  R
R227  R
R228  R
R229  R
R238  R
R421  R
R422  R
R423  R
R5311  THA
TP204  TP
TP206  TP
TP207  TP
TP209  TP
TP214  TP
TP216  TP
TP217  TP
TP219  TP
TP224  TP
TP226  TP
TP227  TP
TP229  TP
U?#6  WAKU_DEF_A3
sheet 11
C211  C
C270  CP
C271  CP
C272  C
C273  C
C274  C
C275  C
C276  C
C277  C
C278  C
C279  C
C280  C
C297  CP
C298  CP
C299  C
CN201  B6B-XH-A
CN202  C9E
CN203  B8B-XH-A
CN204  C5G
CN211  C2A
CN212  C2A
CN213  C2A
CN214  C2A
CN215  C2A
CN216  HM-TP08
CN217  HM-TP08
CN218  C2A
CN219  C2A
CN224  HM-TP08
CN225  HM-TP08
CN226  HM-TP08
CN227  HM-TP08
CN228  HM-TP08
IC211  NA  (sections A,B)
PC203  TLX9906
PC204  TLX9906
Q211  MFNG
Q212  MFNG
R247  R
R248  R
R249  R
R250  R
R251  R
R252  R
R253  R
R255  R
R256  R
R257  R
R258  R
R259  R
R268  R
R269  R
R272  R
R273  R
U?#5  WAKU_DEF_A3
sheet 12
C281  C
C282  C
C283  C
C284  C
C442  C
CN220  HM-TP08
CN221  HM-TP08
CN222  HM-TP08
CN223  HM-TP08
D211  D
D212  D
D213  D
D217  D
D218  D
D219  -
D220  D
D221  -
IC212  TLP5231
PC205  TLX9291A
PC206  TLX9291A
PC207  TLX9000
Q213  SSM3K318R
Q214  SSM3K318R
Q215  SSM3K318R
Q216  SSM3K318R
Q219  RN1907_Q1_1  (sections A,B)
Q220  TRN
R260  R
R263  R
R281  R
R282  R
R284  R
R285  R
R286  R
R287  R
R288  R
R289  R
R290  R
R291  R
R292  R
R293  R
TN33  BOX_2
TN34  BOX_2
U?#4  WAKU_DEF_A3
sheet 13
C313  C
C314  C
C315  C
C316  CP
C317  CP
C447  C
D325  D
IC301  IS18
L301  L
PC301  TLX9906
PC302  TLX9000
Q301  MFNAJ_1
Q302  MFNAJ_1
Q317  MFNG
Q318  RN1907_Q1_1  (sections A,B)
R301  R
R302  R
R303  R
R304  R
R307  R
R308  R
R364  R
R365  R
R366  R
R367  R
R370  R
R371  R
R437  R
TN41  BOX_2
TN42  BOX_2
U?#3  WAKU_DEF_A3
sheet 14
C310  C
C318  CP
C319  CP
C320  CP
C321  CP
C322  CP
C323  CP
C324  CP
C325  CP
C326  CP
C327  CP
C328  CP
C329  C
C330  C
C331  C
C332  C
C333  C
C334  C
C335  C
C336  C
C337  C
C338  C
C339  C
C340  C
C341  C
C342  C
C343  C
C349  C
C350  C
C351  CP
C352  CP
C353  CP
C354  CP
C355  CP
C356  CP
C357  CP
C358  CP
C359  C
C360  C
C361  C
C362  C
C363  C
C364  C
C431  C
C433  C
C435  C
C439  C
CN305  C2A
CN308  B2P-VH
CN309  B2P-VH
CN310  B2P-VH
CN329  HM-TP08
CN330  HM-TP08
CN331  HM-TP08
CN332  HM-TP08
CN333  HM-TP08
CN334  HM-TP08
D302  SBD
D303  SBD
D304  SBD
D305  D
D306  SBD
D307  SBD
D308  SBD
IC302  UCC27211A_00
IC313  TC7PZ17FU
IC314  ISO6720_IC13
L302  L
Q304  MFNAJ_1
Q305  MFNAJ_1
Q306  MFNAJ_1
Q307  MFNAJ_1
Q308  MFNAJ_1
Q309  MFNAJ_1
R309  R
R310  R
R311  R
R312  R
R313  R
R314  R
R315  R
R316  R
R317  R
R318  R
R320  R
R321  R
R322  R
R323  R
R324  R
R325  R
R326  R
R327  R
R328  R
R329  R
R338  R
R431  R
R432  R
R433  R
R5411  THA
TP304  TP
TP306  TP
TP307  TP
TP309  TP
TP314  TP
TP316  TP
TP317  TP
TP319  TP
TP324  TP
TP326  TP
TP327  TP
TP329  TP
U?#2  WAKU_DEF_A3
sheet 15
C311  C
C370  CP
C371  CP
C372  C
C373  C
C374  C
C375  C
C376  C
C377  C
C378  C
C379  C
C380  C
C397  CP
C398  CP
C399  C
CN301  B6B-XH-A
CN302  C9E
CN303  B8B-XH-A
CN304  C5G
CN311  C2A
CN312  C2A
CN313  C2A
CN314  C2A
CN315  C2A
CN316  HM-TP08
CN317  HM-TP08
CN318  C2A
CN319  C2A
CN324  HM-TP08
CN325  HM-TP08
CN326  HM-TP08
CN327  HM-TP08
CN328  HM-TP08
IC311  NA  (sections A,B)
PC303  TLX9906
PC304  TLX9906
Q311  MFNG
Q312  MFNG
R347  R
R348  R
R349  R
R350  R
R351  R
R352  R
R353  R
R355  R
R356  R
R357  R
R358  R
R359  R
R368  R
R369  R
R372  R
R373  R
U?#1  WAKU_DEF_A3
sheet 16
C381  C
C382  C
C383  C
C384  C
C443  C
CN320  HM-TP08
CN321  HM-TP08
CN322  HM-TP08
CN323  HM-TP08
D311  D
D312  D
D313  D
D317  D
D318  D
D319  -
D320  D
D321  -
IC312  TLP5231
PC305  TLX9291A
PC306  TLX9291A
PC307  TLX9000
Q313  SSM3K318R
Q314  SSM3K318R
Q315  SSM3K318R
Q316  SSM3K318R
Q319  RN1907_Q1_1  (sections A,B)
Q320  TRN
R360  R
R363  R
R381  R
R382  R
R384  R
R385  R
R386  R
R387  R
R388  R
R389  R
R390  R
R391  R
R392  R
R393  R
TN43  BOX_2
TN44  BOX_2
U?#16  WAKU_DEF_A3

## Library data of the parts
C213 C313 C438 C439 = C: COMPONENTKIND: 0; COMPONENTTYPE: 4; SIZECODESMD: 3216; VAL1: 0.1u(K); VAL2: 100V
C214 C314 = C: COMPONENTKIND: 0; COMPONENTTYPE: 4; SIZECODESMD: 2012; VAL1: 33n(J); VAL2: 50V
C215 C315 = C: COMPONENTKIND: 0; COMPONENTTYPE: 4; SIZECODESMD: 1608; VAL1: 1000p(K); VAL2: 50V
C216 C217 C316 C317 = CP: COMP: C; COMPONENTTYPE: 4; VAL1: 150u(M); VAL2: 80V
C446 C447 = C: COMPONENTKIND: 0; COMPONENTTYPE: 4; SIZECODESMD: 1608; VAL1: 47n(K); VAL2: 100V
D324 D325 = D: COMPONENTTYPE: 4; USERCOMPTEXT3: TOSHIBA; VAL3: 1SS403E
IC201 IC301 = IS18: COMP: LTC4364HMS-2#PBF; COMPONENTTYPE: 4; SAVECOUNT: 3; VAL3: LTC4364HMS-2#PBF
L201 L301 = L: COMP: XAL1580-401MED; COMPONENTTYPE: 4; SAVECOUNT: 0; VAL1: 0.4u(M); VAL2: 47A; VAL3: XAL1580-401MED
PC201 PC203 PC204 PC301 PC303 PC304 = TLX9906: COMPONENTTYPE: 4; USERCOMPTEXT3: TOSHIBA
PC202 PC207 PC302 PC307 = TLX9000: COMPONENTTYPE: 4; USERCOMPTEXT3: TOSHIBA
Q201 Q202 Q204-Q209 Q301 Q302 Q304-Q309 = MFNAJ_1: COMP: XPW4R10ANB; COMPONENTTYPE: 4; USERCOMPTEXT3: TOSHIBA; VAL3: XPW4R10ANB
Q211 Q212 Q217 Q311 Q312 Q317 = MFNG: COMP: SSM3K361TU; COMPONENTTYPE: 4; USERCOMPTEXT3: TOSHIBA; VAL3: SSM3K361TU
Q218 = RN1907_Q1_1: COMP: RN1907; COMPONENTNAME: RN1907_1; COMPONENTTYPE: 8; CaptureCellPackProp: RN1907_Q1_1B; FUNCN: RN1907_2; USERCOMPTEXT3: TOSHIBA; VAL3: RN1907
R201 R301 = R: COMPONENTKIND: 0; COMPONENTTYPE: 4; FUNCN: R1; SIZECODESMD: 2012; VAL1: 10(J)
R202 R302 = R: COMPONENTKIND: 0; COMPONENTTYPE: 4; FUNCN: R2; SIZECODESMD: 1608; VAL1: 100k(D)
R203 R303 = R: COMPONENTKIND: 0; COMPONENTTYPE: 4; FUNCN: R3; SIZECODESMD: 1608; VAL1: 0
R204 R304 = R: COMPONENTKIND: 0; COMPONENTTYPE: 4; FUNCN: R4; SIZECODESMD: 1608; VAL1: 1.8k(D)
R207 R307 = R: COMPONENTKIND: 0; COMPONENTTYPE: 4; FUNCN: R7; SIZECODESMD: 1608; VAL1: 1M(F)
R208 R308 = R: COMPONENTKIND: 0; COMPONENTTYPE: 4; FUNCN: R108; SIZECODESMD: 10052; VAL1: 1m(F)
R264 R364 = R: COMPONENTKIND: 0; COMPONENTTYPE: 4; FUNCN: R64; SIZECODESMD: 1608; VAL1: 100k(J)
R265 R365 = R: COMPONENTKIND: 0; COMPONENTTYPE: 4; FUNCN: R65; SIZECODESMD: 1608; VAL1: 100k(J)
R266 R366 = R: COMPONENTKIND: 0; COMPONENTTYPE: 4; FUNCN: R66; SIZECODESMD: 1608; VAL1: 33k(J)
R267 R367 = R: COMPONENTKIND: 0; COMPONENTTYPE: 4; FUNCN: R67; SIZECODESMD: 1608; VAL1: 360(J)
R270 R370 = R: COMPONENTKIND: 0; COMPONENTTYPE: 4; FUNCN: R70; SIZECODESMD: 1608; VAL1: 1.5k(J)
R271 R371 = R: COMPONENTKIND: 0; COMPONENTTYPE: 4; FUNCN: R71; SIZECODESMD: 1608; VAL1: 33k(J)
R436 R437 = R: COMPONENTKIND: 0; COMPONENTTYPE: 4; SIZECODESMD: 2012; VAL1: 100(F); VAL2: 125mW
TN31-TN34 TN41-TN44 = BOX_2: COMP: TN; COMPONENTTYPE: 4
U?#7 = WAKU_DEF_A3: AUTHOR: sptcae09; COMPONENTTYPE: 2; DATE: 2025/02/21; DRAWINGNUMBER: RD210-SCHEMATIC1-01; FUNCTION: 48V Input/Output Circuit(BLOCK 2); REVISION: 01; SAVECOUNT: 19; SHEETNUMBER: 9/16; SHTSAVECOUNT: 58; TIME: 10:17:42; TITLE: Automotive 3kW 48V-12V Bidirectional / DC-DC Converter; UPDATEDATE: 2025.2.21; UPDATETIME: 12:17:45
C210 C238-C240 C273 C274 C277 C283 C310 C338-C340 C373 C374 C377 C383 = C: COMPONENTKIND: 0; COMPONENTTYPE: 4; SIZECODESMD: 1608; VAL1: 0.1u(K); VAL2: 50V
C218-C228 C318-C328 = CP: COMP: C; COMPONENTTYPE: 4; VAL1: 47uF(M); VAL2: 63V
C229-C234 C259-C264 C329-C334 C359-C364 = C: COMPONENTKIND: 0; COMPONENTTYPE: 4; SIZECODESMD: 5750; VAL1: 4.7u(M); VAL2: 100V
C235 C236 C281 C335 C336 C381 = C: COMPONENTKIND: 0; COMPONENTTYPE: 4; SIZECODESMD: 5750; VAL1: 10u(K); VAL2: 50V
C237 C241 C272 C275 C278 C299 C337 C341 C372 C375 C378 C399 = C: COMPONENTKIND: 0; COMPONENTTYPE: 4; SIZECODESMD: 3225; VAL1: 2.2u(K); VAL2: 50V
C242 C243 C249 C250 C342 C343 C349 C350 = C: COMPONENTKIND: 0; COMPONENTTYPE: 4; SIZECODESMD: 1608; VAL1: 4.7n(J); VAL2: 50V
C251-C256 C351-C356 = CP: COMP: C; COMPONENTTYPE: 4; VAL1: 39uF(M); VAL2: 63V
C257 C258 C357 C358 = CP: COMP: C; COMPONENTTYPE: 4; VAL1: 150uF(M); VAL2: 63V
C421 C423 C431 C433 = C: COMPONENTKIND: 0; COMPONENTTYPE: 4; SIZECODESMD: 3216; VAL1: 0.033u(J); VAL2: 50V
C425 C435 = C: COMPONENTKIND: 0; COMPONENTTYPE: 4; SIZECODESMD: 3216; VAL1: 0.1u(K); VAL2: 50V
CN205 CN305 = C2A: COMP: B2B-EH; COMPONENTTYPE: 4; VAL3: B2B-EH
CN208-CN210 CN308-CN310 = B2P-VH: COMPONENTTYPE: 4
CN216 CN217 CN220 CN223 CN229-CN232 CN234 CN316 CN317 CN320 CN323 CN329-CN332 CN334 = HM-TP08: COMP: TSW-101-07-G-S; COMPONENTTYPE: 4; VAL3: TSW-101-07-G-S
CN233 CN333 = HM-TP08: COMP: TSW-101-07-G-S; COMPONENTTYPE: 4; NOTMOUNT: NOT MOUNT; VAL3: TSW-101-07-G-S
D202-D204 D206-D208 D302-D304 D306-D308 = SBD: COMP: CMS10130A; COMPONENTTYPE: 4; USERCOMPTEXT3: TOSHIBA; VAL3: CMS10I30A
D205 D305 = D#1: COMP: NRVUA120VT3G; COMPONENTTYPE: 4; CaptureCellPackProp: D##1; VAL3: NRVUA120VT3G
IC202 IC302 = UCC27211A_00: COMP: UCC27211A-Q1; COMPONENTTYPE: 4; VAL3: UCC27211A-Q1
IC213 IC313 = TC7PZ17FU: COMPONENTTYPE: 4; SAVECOUNT: 3; USERCOMPTEXT3: TOSHIBA
IC214 IC314 = ISO6720_IC13: COMP: ISO6720; COMPONENTTYPE: 4; VAL3: ISO6720
L202 L302 = L: COMP: IHXL-1500VZ-5A; COMPONENTKIND: 116; COMPONENTTYPE: 4; DATE: 2024/5/22; SAVEAREA0: -14227,-538,38802,29317; SAVECOUNT: 24; VAL1: 2.2uH; VAL2: 115A; VAL3: IHXL-1500VZ-5A
R209 R309 = R: COMPONENTKIND: 0; COMPONENTTYPE: 4; FUNCN: R9; SIZECODESMD: 2012; VAL1: 2.2(J)
R210 R310 = R: COMPONENTKIND: 0; COMPONENTTYPE: 4; FUNCN: R10; SIZECODESMD: 2012; VAL1: 1(J)
R211 R311 = R: COMPONENTKIND: 0; COMPONENTTYPE: 4; FUNCN: R11; SIZECODESMD: 2012; VAL1: 10(J)
R212 R312 = R: COMPONENTKIND: 0; COMPONENTTYPE: 4; FUNCN: R12; SIZECODESMD: 1608; VAL1: 10k(J)
R213 R313 = R: COMPONENTKIND: 0; COMPONENTTYPE: 4; FUNCN: R13; SIZECODESMD: 2012; VAL1: 1(J)
R214 R314 = R: COMPONENTKIND: 0; COMPONENTTYPE: 4; FUNCN: R14; SIZECODESMD: 2012; VAL1: 10(J)
R215 R315 = R: COMPONENTKIND: 0; COMPONENTTYPE: 4; FUNCN: R15; SIZECODESMD: 1608; VAL1: 10k(J)
R216 R316 = R: COMPONENTKIND: 0; COMPONENTTYPE: 4; FUNCN: R16; SIZECODESMD: 2012; VAL1: 1(J)
R217 R317 = R: COMPONENTKIND: 0; COMPONENTTYPE: 4; FUNCN: R17; SIZECODESMD: 2012; VAL1: 10(J)
R218 R318 = R: COMPONENTKIND: 0; COMPONENTTYPE: 4; FUNCN: R18; SIZECODESMD: 1608; VAL1: 10k(J)
R220 R320 = R: COMPONENTKIND: 0; COMPONENTTYPE: 4; FUNCN: R20; SIZECODESMD: 2012; VAL1: 1(J)
R221 R321 = R: COMPONENTKIND: 0; COMPONENTTYPE: 4; FUNCN: R21; SIZECODESMD: 2012; VAL1: 10(J)
R222 R322 = R: COMPONENTKIND: 0; COMPONENTTYPE: 4; FUNCN: R22; SIZECODESMD: 1608; VAL1: 10k(J)
R223 R323 = R: COMPONENTKIND: 0; COMPONENTTYPE: 4; FUNCN: R23; SIZECODESMD: 2012; VAL1: 1(J)
R224 R324 = R: COMPONENTKIND: 0; COMPONENTTYPE: 4; FUNCN: R24; SIZECODESMD: 2012; VAL1: 10(J)
R225 R325 = R: COMPONENTKIND: 0; COMPONENTTYPE: 4; FUNCN: R25; SIZECODESMD: 1608; VAL1: 10k(J)
R226 R326 = R: COMPONENTKIND: 0; COMPONENTTYPE: 4; FUNCN: R26; SIZECODESMD: 2012; VAL1: 1(J)
R227 R327 = R: COMPONENTKIND: 0; COMPONENTTYPE: 4; FUNCN: R27; SIZECODESMD: 2012; VAL1: 10(J)
R228 R328 = R: COMPONENTKIND: 0; COMPONENTTYPE: 4; FUNCN: R28; SIZECODESMD: 1608; VAL1: 10k(J)
R229 R329 = R: COMPONENTKIND: 0; COMPONENTTYPE: 4; FUNCN: R29; SIZECODESMD: 10052; VAL1: 0.5m(F)
R238 R338 = R: COMPONENTKIND: 0; COMPONENTTYPE: 4; FUNCN: R38; SIZECODESMD: 10052; VAL1: 0.5m(F)
R421 R422 R431 R432 = R: COMPONENTKIND: 0; COMPONENTTYPE: 4; SIZECODESMD: 1608; VAL1: 0
R423 R433 = R: COMPONENTKIND: 0; COMPONENTTYPE: 4; SIZECODESMD: 1608; VAL1: 68k(F)
R5311 R5411 = THA: COMP: TH; COMPONENTTYPE: 4; VAL3: TD11-3H103FT
TP204 TP206 TP207 TP209 TP214 TP216 TP217 TP219 TP224 TP226 TP227 TP229 TP304 TP306 TP307 TP309 TP314 TP316 TP317 TP319 TP324 TP326 TP327 TP329 = TP: COMPONENTTYPE: 4
U?#6 = WAKU_DEF_A3: AUTHOR: e5025010; COMPONENTTYPE: 2; DATE: 2025/02/21; DRAWINGNUMBER: RD210-SCHEMATIC1-01; FUNCTION: Bidirectional DC-DC Converter (BLOCK 2); REVISION: 01; SAVECOUNT: 19; SHEETNUMBER: 10/16; SHTSAVECOUNT: 76; TIME: 19:56:22; TITLE: Automotive 3kW 48V-12V Bidirectional / DC-DC Converter; UPDATEDATE: 2025.2.21; UPDATETIME: 12:09:34
C211 C276 C279 C280 C311 C376 C379 C380 = C: COMPONENTKIND: 0; COMPONENTTYPE: 4; SIZECODESMD: 1608; VAL1: 470p(J); VAL2: 50V
C270 C271 C297 C298 C370 C371 C397 C398 = CP: COMP: C; COMPONENTTYPE: 4; VAL1: 220u(M); VAL2: 10V
CN201 CN301 = B6B-XH-A: COMPONENTTYPE: 4; SAVECOUNT: 10
CN202 CN302 = C9E: COMP: B9B-XH-A; COMPONENTTYPE: 4; VAL3: B9B|XH-A
CN203 CN303 = B8B-XH-A: COMPONENTTYPE: 4
CN204 CN304 = C5G: COMP: B5B-XH-A; COMPONENTTYPE: 4; VAL3: B5B-XH-A
CN211-CN215 CN218 CN219 CN311-CN315 CN318 CN319 = C2A: COMP: TSM-102-01-L-SV; COMPONENTTYPE: 4; VAL3: TSM-102-01-L-SV
CN221 CN222 CN224-CN228 CN321 CN322 CN324-CN328 = HM-TP08: COMP: HW-1-S; COMPONENTTYPE: 4; VAL3: HW-1-S
IC211 IC311 = TLC2272A-Q1_1: COMP: TLC2272A; COMPONENTNAME: T1C2272A_1; COMPONENTTYPE: 8; CaptureCellPackProp: TLC2272A-Q1_1A; FUNCN: TLC2272A_1; SAVECOUNT: 8; VAL3: TLC2272A-Q1
R247 R347 = R: COMPONENTKIND: 0; COMPONENTTYPE: 4; FUNCN: R47; SIZECODESMD: 1608; VAL1: 10(D)
R248 R348 = R: COMPONENTKIND: 0; COMPONENTTYPE: 4; FUNCN: R48; SIZECODESMD: 1608; VAL1: 20k(D)
R249 R349 = R: COMPONENTKIND: 0; COMPONENTTYPE: 4; FUNCN: R49; SIZECODESMD: 1608; VAL1: 20k(D)
R250 R350 = R: COMPONENTKIND: 0; COMPONENTTYPE: 4; FUNCN: R50; SIZECODESMD: 1608; VAL1: 1k(D)
R251 R351 = R: COMPONENTKIND: 0; COMPONENTTYPE: 4; FUNCN: R51; SIZECODESMD: 1608; VAL1: 20k(D)
R252 R352 = R: COMPONENTKIND: 0; COMPONENTTYPE: 4; FUNCN: R52; SIZECODESMD: 1608; VAL1: 20k(D)
R253 R353 = R: COMPONENTKIND: 0; COMPONENTTYPE: 4; FUNCN: R53; SIZECODESMD: 1608; VAL1: 1k(D)
R255 R355 = R: COMPONENTKIND: 0; COMPONENTTYPE: 4; FUNCN: R55; SIZECODESMD: 1608; VAL1: 10(D)
R256 R356 = R: COMPONENTKIND: 0; COMPONENTTYPE: 4; FUNCN: R56; SIZECODESMD: 1608; VAL1: 11k(D)
R257 R357 = R: COMPONENTKIND: 0; COMPONENTTYPE: 4; FUNCN: R57; SIZECODESMD: 1608; VAL1: 1k(D)
R258 R358 = R: COMPONENTKIND: 0; COMPONENTTYPE: 4; FUNCN: R58; SIZECODESMD: 1608; VAL1: 11k(D)
R259 R359 = R: COMPONENTKIND: 0; COMPONENTTYPE: 4; FUNCN: R59; SIZECODESMD: 1608; VAL1: 1k(D)
R268 R368 = R: COMPONENTKIND: 0; COMPONENTTYPE: 4; FUNCN: R68; SIZECODESMD: 1608; VAL1: 33k(J)
R269 R369 = R: COMPONENTKIND: 0; COMPONENTTYPE: 4; FUNCN: R69; SIZECODESMD: 1608; VAL1: 360(J)
R272 R372 = R: COMPONENTKIND: 0; COMPONENTTYPE: 4; FUNCN: R72; SIZECODESMD: 1608; VAL1: 360(J)
R273 R373 = R: COMPONENTKIND: 0; COMPONENTTYPE: 4; FUNCN: R73; SIZECODESMD: 1608; VAL1: 33k(J)
U?#5 = WAKU_DEF_A3: AUTHOR: sptcae09; COMPONENTTYPE: 2; DATE: 2025/02/21; DRAWINGNUMBER: RD210-SCHEMATIC1-01; FUNCTION: Connector and Isolator (Block 2); REVISION: 01; SAVECOUNT: 19; SHEETNUMBER: 11/16; SHTSAVECOUNT: 67; TIME: 10:18:21; TITLE: Automotive 3kW 48V-12V Bidirectional / DC-DC Converter; UPDATEDATE: 2025.2.21; UPDATETIME: 12:37:18
C282 C284 C382 C384 = C: COMPONENTKIND: 0; COMPONENTTYPE: 4; SIZECODESMD: 1608; VAL1: 10n(J); VAL2: 50V
C442 C443 = C: COMPONENTKIND: 0; COMPONENTTYPE: 4; SIZECODESMD: 1608; VAL1: 22n(K); VAL2: 50V
D211-D213 D217 D218 D220 D311-D313 D317 D318 D320 = D#1: COMPONENTTYPE: 4; CaptureCellPackProp: D##1; USERCOMPTEXT3: TOSHIBA; VAL3: 1SS403E
D219 D221 D319 D321 = BZX84C10_SOT_2: COMP: EDZVFH15B; COMPONENTTYPE: 4; VAL3: EDZVFH15B
IC212 IC312 = TPD7106F: COMPONENTTYPE: 4; USERCOMPTEXT3: TOSHIBA
PC205 PC206 PC305 PC306 = TLX9291A: COMPONENTTYPE: 4; USERCOMPTEXT3: TOSHIBA
Q213-Q216 Q313-Q316 = XPW4R10ANB_Q1: COMP: XPQR3004PB; COMPONENTTYPE: 4; SAVECOUNT: 7; USERCOMPTEXT3: TOSHIBA; VAL3: XPQR3004PB
Q219 Q319 = RN1907_Q1_1: COMP: RN1907; COMPONENTNAME: RN1907_2; COMPONENTTYPE: 8; CaptureCellPackProp: RN1907_Q1_1B; FUNCN: RN1907_2; USERCOMPTEXT3: TOSHIBA; VAL3: RN1907
Q220 Q320 = TRN: COMP: 2SC4117-GR; COMPONENTTYPE: 4; USERCOMPTEXT3: TOSHIBA; VAL3: 2SC4117-GR
R260 R360 = R: COMPONENTKIND: 0; COMPONENTTYPE: 4; FUNCN: R60; SIZECODESMD: 2012; VAL1: 2.2(J)
R263 R363 = R: COMPONENTKIND: 0; COMPONENTTYPE: 4; FUNCN: R63; SIZECODESMD: 1608; VAL1: 330k(F)
R281 R381 = R: COMPONENTKIND: 0; COMPONENTTYPE: 4; FUNCN: R81; SIZECODESMD: 1608; VAL1: 47k(J)
R282 R382 = R: COMPONENTKIND: 0; COMPONENTTYPE: 4; FUNCN: R82; SIZECODESMD: 2012; VAL1: 9.1k(J)
R284 R384 = R: COMPONENTKIND: 0; COMPONENTTYPE: 4; FUNCN: R84; SIZECODESMD: 1608; VAL1: 2.2k(J)
R285 R385 = R: COMPONENTKIND: 0; COMPONENTTYPE: 4; FUNCN: R85; SIZECODESMD: 1608; VAL1: 2.2k(J)
R286 R386 = R: COMPONENTKIND: 0; COMPONENTTYPE: 4; FUNCN: R86; SIZECODESMD: 1608; VAL1: 33k(J)
R287 R387 = R: COMPONENTKIND: 0; COMPONENTTYPE: 4; FUNCN: R87; SIZECODESMD: 1608; VAL1: 33k(J)
R288 R388 = R: COMPONENTKIND: 0; COMPONENTTYPE: 4; FUNCN: R88; SIZECODESMD: 1608; VAL1: 47k(J)
R289 R389 = R: COMPONENTKIND: 0; COMPONENTTYPE: 4; FUNCN: R89; SIZECODESMD: 1608; VAL1: 47k(J)
R290 R390 = R: COMPONENTKIND: 0; COMPONENTTYPE: 4; FUNCN: R90; SIZECODESMD: 1608; VAL1: 3.3k(J)
R291 R391 = R: COMPONENTKIND: 0; COMPONENTTYPE: 4; FUNCN: R91; SIZECODESMD: 1608; VAL1: 33k(J)
R292 R392 = R: COMPONENTKIND: 0; COMPONENTTYPE: 4; FUNCN: R92; SIZECODESMD: 1608; VAL1: 47k(J)
R293 R393 = R: COMPONENTKIND: 0; COMPONENTTYPE: 4; FUNCN: R93; SIZECODESMD: 1608; VAL1: 330k(J)
U?#4 = WAKU_DEF_A3: AUTHOR: sptcae09; COMPONENTTYPE: 2; DATE: 2025/02/21; DRAWINGNUMBER: RD210-SCHEMATIC1-01; FUNCTION: 12V Input/Output Circuit (BLOCK 2); REVISION: 01; SAVECOUNT: 19; SHEETNUMBER: 12/16; SHTSAVECOUNT: 58; TIME: 10:17:42; TITLE: Automotive 3kW 48V-12V Bidirectional / DC-DC Converter; UPDATEDATE: 2025.2.21; UPDATETIME: 12:17:45
Q318 = RN1907_Q1_1: COMP: RN1907; COMPONENTNAME: RN1907_1; COMPONENTTYPE: 8; CaptureCellPackProp: RN1907_Q1_1A; FUNCN: RN1907_1; USERCOMPTEXT3: TOSHIBA; VAL3: RN1907
U?#3 = WAKU_DEF_A3: AUTHOR: sptcae09; COMPONENTTYPE: 2; DATE: 2025/02/21; DRAWINGNUMBER: RD210-SCHEMATIC1-01; FUNCTION: 48V Input/Output Circuit(BLOCK 3); REVISION: 01; SAVECOUNT: 19; SHEETNUMBER: 13/16; SHTSAVECOUNT: 61; TIME: 10:17:42; TITLE: Automotive 3kW 48V-12V Bidirectional / DC-DC Converter; UPDATEDATE: 2025.2.21; UPDATETIME: 12:17:46
U?#2 = WAKU_DEF_A3: AUTHOR: e5025010; COMPONENTTYPE: 2; DATE: 2025/02/21; DRAWINGNUMBER: RD210-SCHEMATIC1-01; FUNCTION: Bidirectional DC-DC Converter (BLOCK 3); REVISION: 01; SAVECOUNT: 19; SHEETNUMBER: 14/16; SHTSAVECOUNT: 78; TIME: 20:10:16; TITLE: Automotive 3kW 48V-12V Bidirectional / DC-DC Converter; UPDATEDATE: 2025.2.21; UPDATETIME: 12:09:35
U?#1 = WAKU_DEF_A3: AUTHOR: sptcae09; COMPONENTTYPE: 2; DATE: 2025/02/21; DRAWINGNUMBER: RD210-SCHEMATIC1-01; FUNCTION: Connector and Isolator (Block 3); REVISION: 01; SAVECOUNT: 19; SHEETNUMBER: 15/16; SHTSAVECOUNT: 63; TIME: 10:18:21; TITLE: Automotive 3kW 48V-12V Bidirectional / DC-DC Converter; UPDATEDATE: 2025.2.21; UPDATETIME: 12:17:46
U?#16 = WAKU_DEF_A3: AUTHOR: sptcae09; COMPONENTTYPE: 2; DATE: 2025/02/21; DRAWINGNUMBER: RD210-SCHEMATIC1-01; FUNCTION: 12V Input/Output Circuit (BLOCK 3); REVISION: 01; SAVECOUNT: 19; SHEETNUMBER: 16/16; SHTSAVECOUNT: 56; TIME: 10:17:42; TITLE: Automotive 3kW 48V-12V Bidirectional / DC-DC Converter; UPDATEDATE: 2025.2.21; UPDATETIME: 12:09:34

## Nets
GND-3: C210.1 C272.2 C273.2 C274.2 C275.2 C277.1 C278.1 CN201.3 CN202.9 CN203.3 CN204.4 IC211.4 IC214.4 PC202.3 PC207.3 Q218.1 Q218.4 Q219.1 Q219.4
GND-4: C310.1 C372.2 C373.2 C374.2 C375.2 C377.1 C378.1 CN301.3 CN302.9 CN303.3 CN304.4 IC311.4 IC314.4 PC302.3 PC307.3 Q318.1 Q318.4 Q319.1 Q319.4
GND_5V_I2_0: C298.2(1) CN227.1
GND_5V_I2_1: C270.2(1) CN225.1
GND_5V_I2_2: C297.2(1) CN226.1
GND_5V_I3_0: C398.2(1) CN327.1
GND_5V_I3_1: C370.2(1) CN325.1
GND_5V_I3_2: C397.2(1) CN326.1
GND_12R0_SYS_I2_0: C299.2 CN228.1
GND_12R0_SYS_I2_1: C271.2(1) CN224.1
GND_12R0_SYS_I3_0: C399.2 CN328.1
GND_12R0_SYS_I3_1: C371.2(1) CN324.1
GND_P-3: C211.1 C213.1 C214.2 C215.1 C216.2(1) C217.2(1) C218.2(1) C219.2(1) C220.2(1) C221.2(1) C222.2(1) C223.2(1) C224.2(1) C225.2(1) C226.2(1) C227.2(1) C228.2(1) C229.1 C230.1 C231.1 C232.1 C233.1 C234.1 C235.1 C236.1 C237.2 C238.2 C239.1 C240.1 C242.2 C243.2 C249.2 C250.2 C251.2(1) C252.2(1) C253.2(1) C254.2(1) C255.2(1) C256.2(1) C257.2(1) C258.2(1) C259.1 C260.1 C261.1 C262.1 C263.1 C264.1 C279.1 C281.1 C283.2 C442.2 C446.2 CN201.6 CN203.1 CN216.1 CN217.1 CN220.1 CN234.1 D217.1(A) IC201.12 IC201.16 IC202.7(VSS) IC202.9(GND) IC212.2(TEST) IC212.7(IN2) IC212.8(GND1) IC212.9(GND2) IC213.2 IC214.5 Q207.S Q208.S Q209.S R204.1 R222.2 R225.2 R228.2 R250.2 R251.1 R257.2 R258.1 R265.1 R288.1 R289.1 R293.1 TN32.1(spin.1) TN32.2(spin.2) TN34.1(spin.1) TN34.2(spin.2) TP217.1 TP219.1
GND_P-4: C311.1 C313.1 C314.2 C315.1 C316.2(1) C317.2(1) C318.2(1) C319.2(1) C320.2(1) C321.2(1) C322.2(1) C323.2(1) C324.2(1) C325.2(1) C326.2(1) C327.2(1) C328.2(1) C329.1 C330.1 C331.1 C332.1 C333.1 C334.1 C335.1 C336.1 C337.2 C338.2 C339.1 C340.1 C342.2 C343.2 C349.2 C350.2 C351.2(1) C352.2(1) C353.2(1) C354.2(1) C355.2(1) C356.2(1) C357.2(1) C358.2(1) C359.1 C360.1 C361.1 C362.1 C363.1 C364.1 C379.1 C381.1 C383.2 C443.2 C447.2 CN301.6 CN303.1 CN316.1 CN317.1 CN320.1 CN334.1 D317.1(A) IC301.12 IC301.16 IC302.7(VSS) IC302.9(GND) IC312.2(TEST) IC312.7(IN2) IC312.8(GND1) IC312.9(GND2) IC313.2 IC314.5 Q307.S Q308.S Q309.S R304.1 R322.2 R325.2 R328.2 R350.2 R351.1 R357.2 R358.1 R365.1 R388.1 R389.1 R393.1 TN42.1(spin.1) TN42.2(spin.2) TN44.1(spin.1) TN44.2(spin.2) TP317.1 TP319.1
VDDA-3: C277.2 C278.2 CN204.5 IC211.8
VDDA-4: C377.2 C378.2 CN304.5 IC311.8
VDDIO-3: C210.2 C272.1 C273.1 CN201.1 IC214.1
VDDIO-4: C310.2 C372.1 C373.1 CN301.1 IC314.1
DIAG_0-3: CN203.6 PC207.4
DIAG_0-4: CN303.6 PC307.4
H_EN_0-3: CN204.3 Q218.2
H_EN_0-4: CN304.3 Q318.2
L_IN1_0-3: CN203.4 Q219.2
L_IN1_0-4: CN303.4 Q319.2
MES_EN_0-3: CN202.8 Q218.5
MES_EN_0-4: CN302.8 Q318.5
PowerGood_0-3: CN204.1 PC202.4
PowerGood_0-4: CN304.1 PC302.4
PWM_H_0-3: CN202.2 IC214.2
PWM_H_0-4: CN302.2 IC314.2
PWM_L_0-3: CN202.1 IC214.3
PWM_L_0-4: CN302.1 IC314.3
Q218-C-3pin: Q218.3 R269.1 R272.1
Q318-C-3pin: Q318.3 R369.1 R372.1
SIG00935: Q217.3(D) R264.1
SIG00937: IC201.9 IC201.10 PC201.4(3) Q217.2(S) R265.2
SIG00938: IC201.13 R270.1
SIG00939: C213.2 IC201.8 R201.1 R264.2
SIG00940: D324.2(A) IC201.6 Q201.G Q202.G R207.1 R436.1
SIG00941: PC202.2 R270.2 R271.1
SIG00942: C214.1 IC201.15
SIG00943: PC201.6(4) Q217.1(G)
SIG00944: C215.2 IC201.11 R202.1 R203.2
SIG00945: IC201.2 IC201.5 Q201.S Q202.S R207.2 R208.1
SIG00946: PC201.3(2) R266.1 R267.1
SIG00947: C216.1(2) C217.1(2) IC201.1 L201.1 R208.2
SIG00948: R203.1 R204.2
SIG00949: Q218.6 R267.2
SIG00950: C446.1 D324.1(C) R436.2
SIG01068: C423.1 CN209.2 R422.2
SIG01070: C249.1 C425.2 CN210.1 L202.2 R238.1 R422.1
SIG01071: D208.1(A) R226.1
SIG01072: IC213.3 IC214.6
SIG01073: C241.2 C438.2 CN231.1 CN233.1 IC202.4(HS) L202.1 Q204.S Q205.S Q206.S Q207.D Q208.D Q209.D R212.2 R215.2 R218.2 R423.1 TP207.1 TP209.1 TP214.1 TP216.1
SIG01074: D202.2(C) D203.2(C) D204.2(C) IC202.3(HO) R211.1 R214.1 R217.1
SIG01075: C242.1 CN230.1 Q204.D Q205.D Q206.D R229.2 R421.1 TP204.1 TP206.1
SIG01076: CN232.1 Q208.G R223.2 R224.2 R225.1
SIG01077: C425.1 CN210.2 R423.2
SIG01078: D203.1(A) R213.1
SIG01079: IC202.6(LI) IC213.4
SIG01080: CN229.1 Q205.G R213.2 R214.2 R215.1
SIG01081: Q206.G R216.2 R217.2 R218.1 TP226.1
SIG01082: Q204.G R210.2 R211.2 R212.1 TP224.1
SIG01083: Q207.G R220.2 R221.2 R222.1 TP227.1
SIG01084: C241.1 C438.1 D205.2(C) IC202.2(HB)
SIG01085: D202.1(A) R210.1
SIG01086: D207.1(A) R223.1
SIG01087: IC213.1 IC214.7
SIG01088: Q209.G R226.2 R227.2 R228.1 TP229.1
SIG01089: D204.1(A) R216.1
SIG01091: IC202.5(HI) IC213.6
SIG01092: D206.1(A) R220.1
SIG01093: D205.1(A) R209.2
SIG01094: D206.2(C) D207.2(C) D208.2(C) IC202.8(LO) R221.1 R224.1 R227.1
SIG01095: C421.2 CN208.2 R421.2
SIG01096: CN205.2 R5311.1
SIG01097: CN205.1 R5311.2
SIG01145: PC203.6(4) Q211.1(G)
SIG01146: PC204.6(4) Q212.1(G)
SIG01147: PC204.3(2) R272.2 R273.1
SIG01149: PC203.3(2) R268.1 R269.2
SIG01150: C280.1 IC211.6 R258.2 R259.1
SIG01151: R248.2 R249.1
SIG01152: C279.2 IC211.5 PC204.4(3) Q212.2(S) R257.1
SIG01153: C276.1 IC211.2(3) R252.2 R253.1
SIG01154: Q212.3(D) R256.2
SIG01155: R251.2 R252.1
SIG01156: Q211.3(D) R249.2
SIG01157: CN219.2 R247.1 R248.1
SIG01158: C271.1(2) CN203.7 CN215.1
SIG01159: C270.1(2) CN203.2 CN214.1
SIG01160: C211.2 IC211.3(2) PC203.4(3) Q211.2(S) R250.1
SIG01161: C297.1(2) CN204.2 CN213.1
SIG01162: CN218.2 R255.1 R256.1
SIG01163: C299.1 CN201.5 CN212.1
SIG01164: C298.1(2) CN201.4 CN211.1
SIG01247: C284.1 IC212.14(CP2)
SIG01248: IC212.12(OUT1) R281.1 R282.1
SIG01249: PC206.2 R285.2 R287.1
SIG01250: C283.1 IC212.13(CPV)
SIG01251: CN222.1 D218.1(A) D221.1(2) Q213.2(S) Q214.2(S) Q215.2(S) Q216.2(S) Q220.2(E) R263.1
SIG01252: IC212.5(STBY) PC205.3 R289.2
SIG01253: PC205.2 R284.2 R286.1
SIG01254: D219.2(1) D221.2(1)
SIG01255: C281.2 IC212.4(VDD) R260.2
SIG01256: Q219.3 R284.1
SIG01257: C284.2 IC212.16(CP2-)
SIG01258: C282.1 IC212.3(CP1)
SIG01259: IC212.10(DIAG) R290.1
SIG01260: CN223.1 D211.2(C) D212.2(C) D213.2(C) R260.1
SIG01261: PC207.2 R290.2 R291.1
SIG01262: D218.2(C) Q220.1(B) R293.2
SIG01263: C442.1 CN221.1 D219.1(2) D220.1(A) Q213.1(G) Q214.1(G) Q215.1(G) Q216.1(G) Q220.3(C) R263.2 R292.2
SIG01264: IC212.6(IN1) PC206.3 R288.2
SIG01265: D217.2(C) R281.2 R292.1
SIG01266: D220.2(C) R282.2
SIG01267: Q219.6 R285.1
SIG01268: C282.2 IC212.1(CP1-)
SIG01334: IC301.2 IC301.5 Q301.S Q302.S R307.2 R308.1
SIG01335: IC301.13 R370.1
SIG01336: R303.1 R304.2
SIG01337: PC302.2 R370.2 R371.1
SIG01338: D325.2(A) IC301.6 Q301.G Q302.G R307.1 R437.1
SIG01339: C316.1(2) C317.1(2) IC301.1 L301.1 R308.2
SIG01340: C313.2 IC301.8 R301.1 R364.2
SIG01341: PC301.3(2) R366.1 R367.1
SIG01342: C314.1 IC301.15
SIG01343: PC301.6(4) Q317.1(G)
SIG01345: IC301.9 IC301.10 PC301.4(3) Q317.2(S) R365.2
SIG01347: Q317.3(D) R364.1
SIG01348: C315.2 IC301.11 R302.1 R303.2
SIG01349: Q318.6 R367.2
SIG01350: C447.1 D325.1(C) R437.2
SIG01463: D306.2(C) D307.2(C) D308.2(C) IC302.8(LO) R321.1 R324.1 R327.1
SIG01464: IC302.5(HI) IC313.6
SIG01465: C342.1 CN330.1 Q304.D Q305.D Q306.D R329.2 R431.1 TP304.1 TP306.1
SIG01466: D304.1(A) R316.1
SIG01467: D306.1(A) R320.1
SIG01468: D305.1(A) R309.2
SIG01469: D302.2(C) D303.2(C) D304.2(C) IC302.3(HO) R311.1 R314.1 R317.1
SIG01471: CN332.1 Q308.G R323.2 R324.2 R325.1
SIG01472: CN329.1 Q305.G R313.2 R314.2 R315.1
SIG01473: Q307.G R320.2 R321.2 R322.1 TP327.1
SIG01474: Q306.G R316.2 R317.2 R318.1 TP326.1
SIG01475: C341.2 C439.2 CN331.1 CN333.1 IC302.4(HS) L302.1 Q304.S Q305.S Q306.S Q307.D Q308.D Q309.D R312.2 R315.2 R318.2 R433.1 TP307.1 TP309.1 TP314.1 TP316.1
SIG01476: D307.1(A) R323.1
SIG01477: D302.1(A) R310.1
SIG01478: D303.1(A) R313.1
SIG01479: C349.1 C435.2 CN310.1 L302.2 R338.1 R432.1
SIG01481: C431.2 CN308.2 R431.2
SIG01482: IC313.3 IC314.6
SIG01483: C435.1 CN310.2 R433.2
SIG01484: Q309.G R326.2 R327.2 R328.1 TP329.1
SIG01485: D308.1(A) R326.1
SIG01486: C433.1 CN309.2 R432.2
SIG01487: Q304.G R310.2 R311.2 R312.1 TP324.1
SIG01488: IC302.6(LI) IC313.4
SIG01489: IC313.1 IC314.7
SIG01490: C341.1 C439.1 D305.2(C) IC302.2(HB)
SIG01491: CN305.2 R5411.1
SIG01492: CN305.1 R5411.2
SIG01545: C311.2 IC311.3(2) PC303.4(3) Q311.2(S) R350.1
SIG01546: C376.1 IC311.2(3) R352.2 R353.1
SIG01548: PC304.6(4) Q312.1(G)
SIG01549: R351.2 R352.1
SIG01550: PC303.6(4) Q311.1(G)
SIG01551: Q312.3(D) R356.2
SIG01552: C370.1(2) CN303.2 CN314.1
SIG01553: PC303.3(2) R368.1 R369.2
SIG01554: Q311.3(D) R349.2
SIG01555: C380.1 IC311.6 R358.2 R359.1
SIG01556: C371.1(2) CN303.7 CN315.1
SIG01557: PC304.3(2) R372.2 R373.1
SIG01558: CN319.2 R347.1 R348.1
SIG01559: C379.2 IC311.5 PC304.4(3) Q312.2(S) R357.1
SIG01560: R348.2 R349.1
SIG01562: C397.1(2) CN304.2 CN313.1
SIG01563: CN318.2 R355.1 R356.1
SIG01564: C399.1 CN301.5 CN312.1
SIG01565: C398.1(2) CN301.4 CN311.1
SIG01646: CN323.1 D311.2(C) D312.2(C) D313.2(C) R360.1
SIG01647: C381.2 IC312.4(VDD) R360.2
SIG01648: CN322.1 D318.1(A) D321.1(2) Q313.2(S) Q314.2(S) Q315.2(S) Q316.2(S) Q320.2(E) R363.1
SIG01649: PC305.2 R384.2 R386.1
SIG01650: Q319.3 R384.1
SIG01651: IC312.5(STBY) PC305.3 R389.2
SIG01652: C384.2 IC312.16(CP2-)
SIG01653: C382.2 IC312.1(CP1-)
SIG01654: C443.1 CN321.1 D319.1(2) D320.1(A) Q313.1(G) Q314.1(G) Q315.1(G) Q316.1(G) Q320.3(C) R363.2 R392.2
SIG01655: IC312.6(IN1) PC306.3 R388.2
SIG01656: Q319.6 R385.1
SIG01657: D317.2(C) R381.2 R392.1
SIG01658: C384.1 IC312.14(CP2)
SIG01659: D318.2(C) Q320.1(B) R393.2
SIG01660: D320.2(C) R382.2
SIG01661: D319.2(1) D321.2(1)
SIG01662: C383.1 IC312.13(CPV)
SIG01663: PC306.2 R385.2 R387.1
SIG01664: IC312.12(OUT1) R381.1 R382.1
SIG01665: PC307.2 R390.2 R391.1
SIG01666: C382.1 IC312.3(CP1)
SIG01667: IC312.10(DIAG) R390.1
STBY_0-3: CN203.5 Q219.5
STBY_0-4: CN303.5 Q319.5
V_B0-3: C276.2 CN202.7 IC211.1 R253.2
V_B0-4: C376.2 CN302.7 IC311.1 R353.2
V_C0-3: C280.2 CN202.6 IC211.7 R259.2
V_C0-4: C380.2 CN302.6 IC311.7 R359.2
VP_5R0-3: C274.1 C275.1 CN201.2 PC201.1 PC203.1 PC204.1 PC205.1 PC206.1 R266.2 R268.2 R273.2 R286.2 R287.2
VP_5R0-4: C374.1 C375.1 CN301.2 PC301.1 PC303.1 PC304.1 PC305.1 PC306.1 R366.2 R368.2 R373.2 R386.2 R387.2
VP_5V_I2_0: C239.2 C240.2 CN211.2 IC213.5 IC214.8
VP_5V_I2_1: CN214.2 PC205.4 PC206.4 PC207.1 R291.2
VP_5V_I2_2: CN213.2 PC202.1 R271.2
VP_5V_I3_0: C339.2 C340.2 CN311.2 IC313.5 IC314.8
VP_5V_I3_1: CN314.2 PC305.4 PC306.4 PC307.1 R391.2
VP_5V_I3_2: CN313.2 PC302.1 R371.2
VP_12R0_SYS_I2_0: C235.2 C236.2 C237.1 C238.1 CN212.2 IC202.1(VDD) R209.1
VP_12R0_SYS_I2_1: CN215.2 D211.1(A)
VP_12R0_SYS_I3_0: C335.2 C336.2 C337.1 C338.1 CN312.2 IC302.1(VDD) R309.1
VP_12R0_SYS_I3_1: CN315.2 D311.1(A)
VP_H: Q201.D Q202.D Q301.D Q302.D R201.2 R202.2 R301.2 R302.2 TN31.1(spin.1) TN31.2(spin.2) TN41.1(spin.1) TN41.2(spin.2) ; also on sheet 12 14 16
VP_H_0-3: C218.1(2) C219.1(2) C220.1(2) C221.1(2) C222.1(2) C223.1(2) C224.1(2) C225.1(2) C226.1(2) C227.1(2) C228.1(2) C229.2 C230.2 C231.2 C232.2 C233.2 C234.2 C243.1 C421.1 CN208.1 CN219.1 L201.2 R229.1 R247.2
VP_H_0-4: C318.1(2) C319.1(2) C320.1(2) C321.1(2) C322.1(2) C323.1(2) C324.1(2) C325.1(2) C326.1(2) C327.1(2) C328.1(2) C329.2 C330.2 C331.2 C332.2 C333.2 C334.2 C343.1 C431.1 CN308.1 CN319.1 L301.2 R329.1 R347.2
VP_L: D213.1(A) D313.1(A) Q215.3(D) Q216.3(D) Q315.3(D) Q316.3(D) TN33.1(spin.1) TN33.2(spin.2) TN43.1(spin.1) TN43.2(spin.2) ; also on sheet 9 13 14
VP_L_0-3: C250.1 C251.1(2) C252.1(2) C253.1(2) C254.1(2) C255.1(2) C256.1(2) C257.1(2) C258.1(2) C259.2 C260.2 C261.2 C262.2 C263.2 C264.2 C423.2 CN203.8 CN209.1 CN218.1 D212.1(A) Q213.3(D) Q214.3(D) R238.2 R255.2
VP_L_0-4: C350.1 C351.1(2) C352.1(2) C353.1(2) C354.1(2) C355.1(2) C356.1(2) C357.1(2) C358.1(2) C359.2 C360.2 C361.2 C362.2 C363.2 C364.2 C433.2 CN303.8 CN309.1 CN318.1 D312.1(A) Q313.3(D) Q314.3(D) R338.2 R355.2

Not connected (* = marked no-connect by the designer): CN202 3 4 5; CN302 3 4 5; IC201 3 4 7 14; IC212 11(OUT2) 15(N.C.); IC301 3 4 7 14; IC312 11(OUT2) 15(N.C.)

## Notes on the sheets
sheet 1
- 2/2
- 1/2
sheet 2
- ¦GND_12R0_SYS_I3_0 is connected to GND_P-4
- ¦GND_5V_I3_0 is connected to GND_P-4
- ¦CN301 is connected to CN301 of RD210-SCHEMATIC2
- ¦
- ¦
- ¦CN302 is connected to CN302 of RD210-SCHEMATIC2
- 1/2
- ¦GND_12R0_SYS_I3_1 is connected to GND_P-4
- ¦GND_5V_I3_1 is connected to GND_P-4
- ¦CN303 is connected to CN303 of RD210-SCHEMATIC2
- ¦
- ¦
- 2/2
- ¦CN304 is connected to CN304 of RD210-SCHEMATIC2
- ¦GND_5V_I3_2 is connected to GND_P-4
- ¦
sheet 3
- ¦CN308 is connected to CN407 of RD210-SCHEMATIC2
- X6
- X11
- ¦CN310 is connected to CN940 of RD210-SCHEMATIC2
- ¦CN309 is connected to CN408 of RD210-SCHEMATIC2
- ¦CN305 is connected to CN305 of RD210-SCHEMATIC2
- X6
- X6
- X2
sheet 4
- 1/2
- 2/2
sheet 5
- 2/2
- 1/2
sheet 6
- ¦GND_12R0_SYS_I2_0 is connected to GND_P-3
- ¦GND_5V_I2_0 is connected to GND_P-3
- ¦CN201 is connected to CN201 of RD210-SCHEMATIC2
- ¦
- ¦
- ¦CN202 is connected to CN202 of RD210-SCHEMATIC2
- 1/2
- ¦GND_12R0_SYS_I2_1 is connected to GND_P-3
- ¦GND_5V_I2_1 is connected to GND_P-3
- ¦CN203 is connected to CN203 of RD210-SCHEMATIC2
- ¦
- ¦
- 2/2
- ¦CN204 is connected to CN204 of RD210-SCHEMATIC2
- ¦GND_5V_I2_2 is connected to GND_P-3
- ¦
sheet 7
- ¦CN208 is connected to CN307 of RD210-SCHEMATIC2
- X6
- X11
- ¦CN210 is connected to CN936 of RD210-SCHEMATIC2
- ¦CN209 is connected to CN308 of RD210-SCHEMATIC2
- ¦CN205 is connected to CN205 of RD210-SCHEMATIC2
- X6
- X6
- X2
sheet 8
- 1/2
- 2/2
